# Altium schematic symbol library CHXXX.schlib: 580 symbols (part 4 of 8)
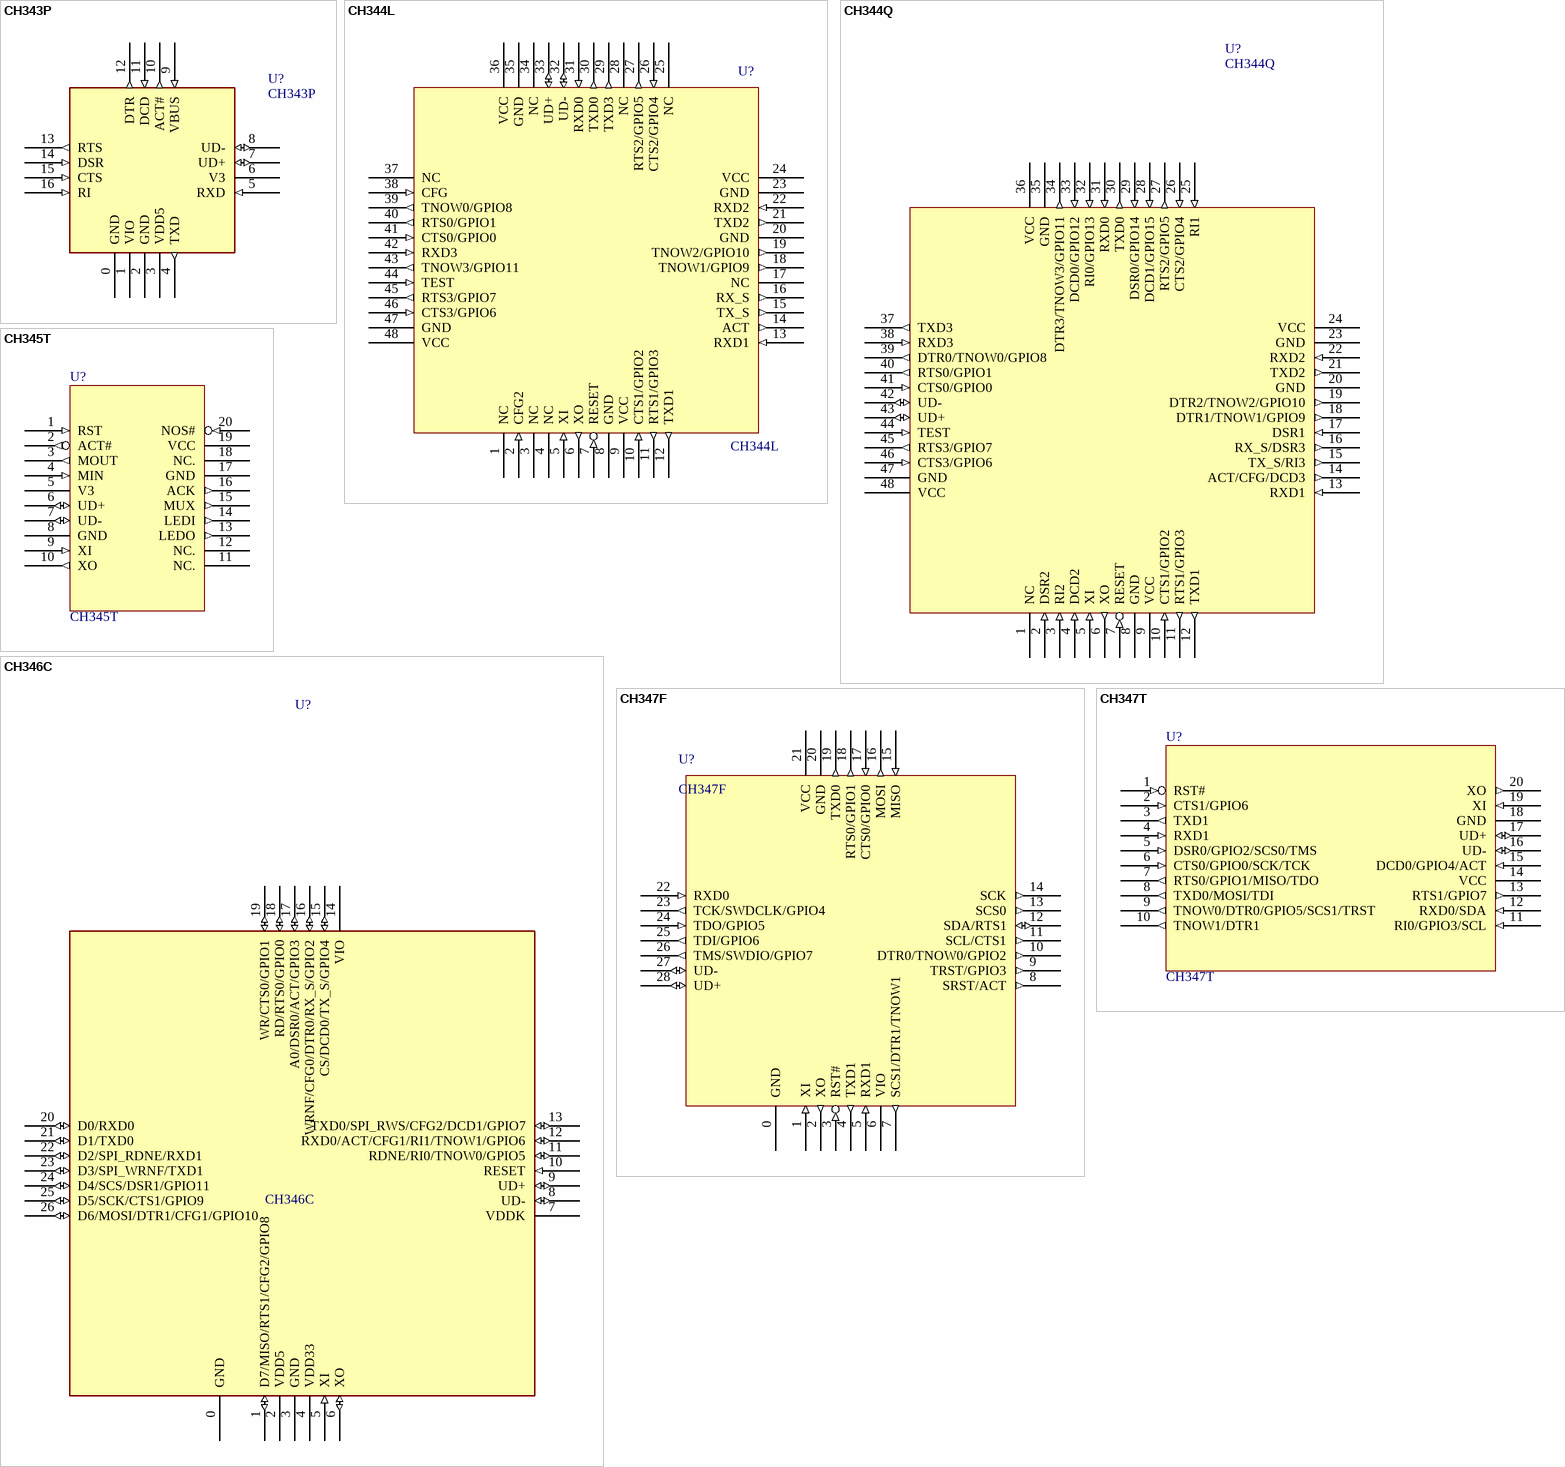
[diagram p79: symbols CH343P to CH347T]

## CH347F
designator U?
High Speed USB to UART + SPI + IIC + JTAG
footprint QFN28_4X4
pins: 0 GND (power), 1 XI (in), 2 XO (out), 3 RST# (in), 4 TXD1 (out), 5 RXD1 (in), 6 VIO (power), 7 SCS1/DTR1/TNOW1 (out), 8 SRST/ACT (out), 9 TRST/GPIO3 (out), 10 DTR0/TNOW0/GPIO2 (out), 11 SCL/CTS1 (out), 12 SDA/RTS1 (io), 13 SCS0 (out), 14 SCK (out), 15 MISO (in), 16 MOSI (out), 17 CTS0/GPIO0 (in), 18 RTS0/GPIO1 (out), 19 TXD0 (out), 20 GND (power), 21 VCC (power), 22 RXD0 (in), 23 TCK/SWDCLK/GPIO4 (out), 24 TDO/GPIO5 (in), 25 TDI/GPIO6 (out), 26 TMS/SWDIO/GPIO7 (out), 27 UD- (io), 28 UD+ (io)

## CH347T
designator U?
High Speed USB to UART / SPI / IIC / JTAG
footprint TSSOP20
pins: 1 RST# (in), 2 CTS1/GPIO6 (in), 3 TXD1 (out), 4 RXD1 (in), 5 DSR0/GPIO2/SCS0/TMS (in), 6 CTS0/GPIO0/SCK/TCK (in), 7 RTS0/GPIO1/MISO/TDO (out), 8 TXD0/MOSI/TDI (out), 9 TNOW0/DTR0/GPIO5/SCS1/TRST (out), 10 TNOW1/DTR1 (out), 11 RI0/GPIO3/SCL (in), 12 RXD0/SDA (in), 13 RTS1/GPIO7 (out), 14 VCC (power), 15 DCD0/GPIO4/ACT (in), 16 UD- (io), 17 UD+ (io), 18 GND (power), 19 XI (in), 20 XO (out)

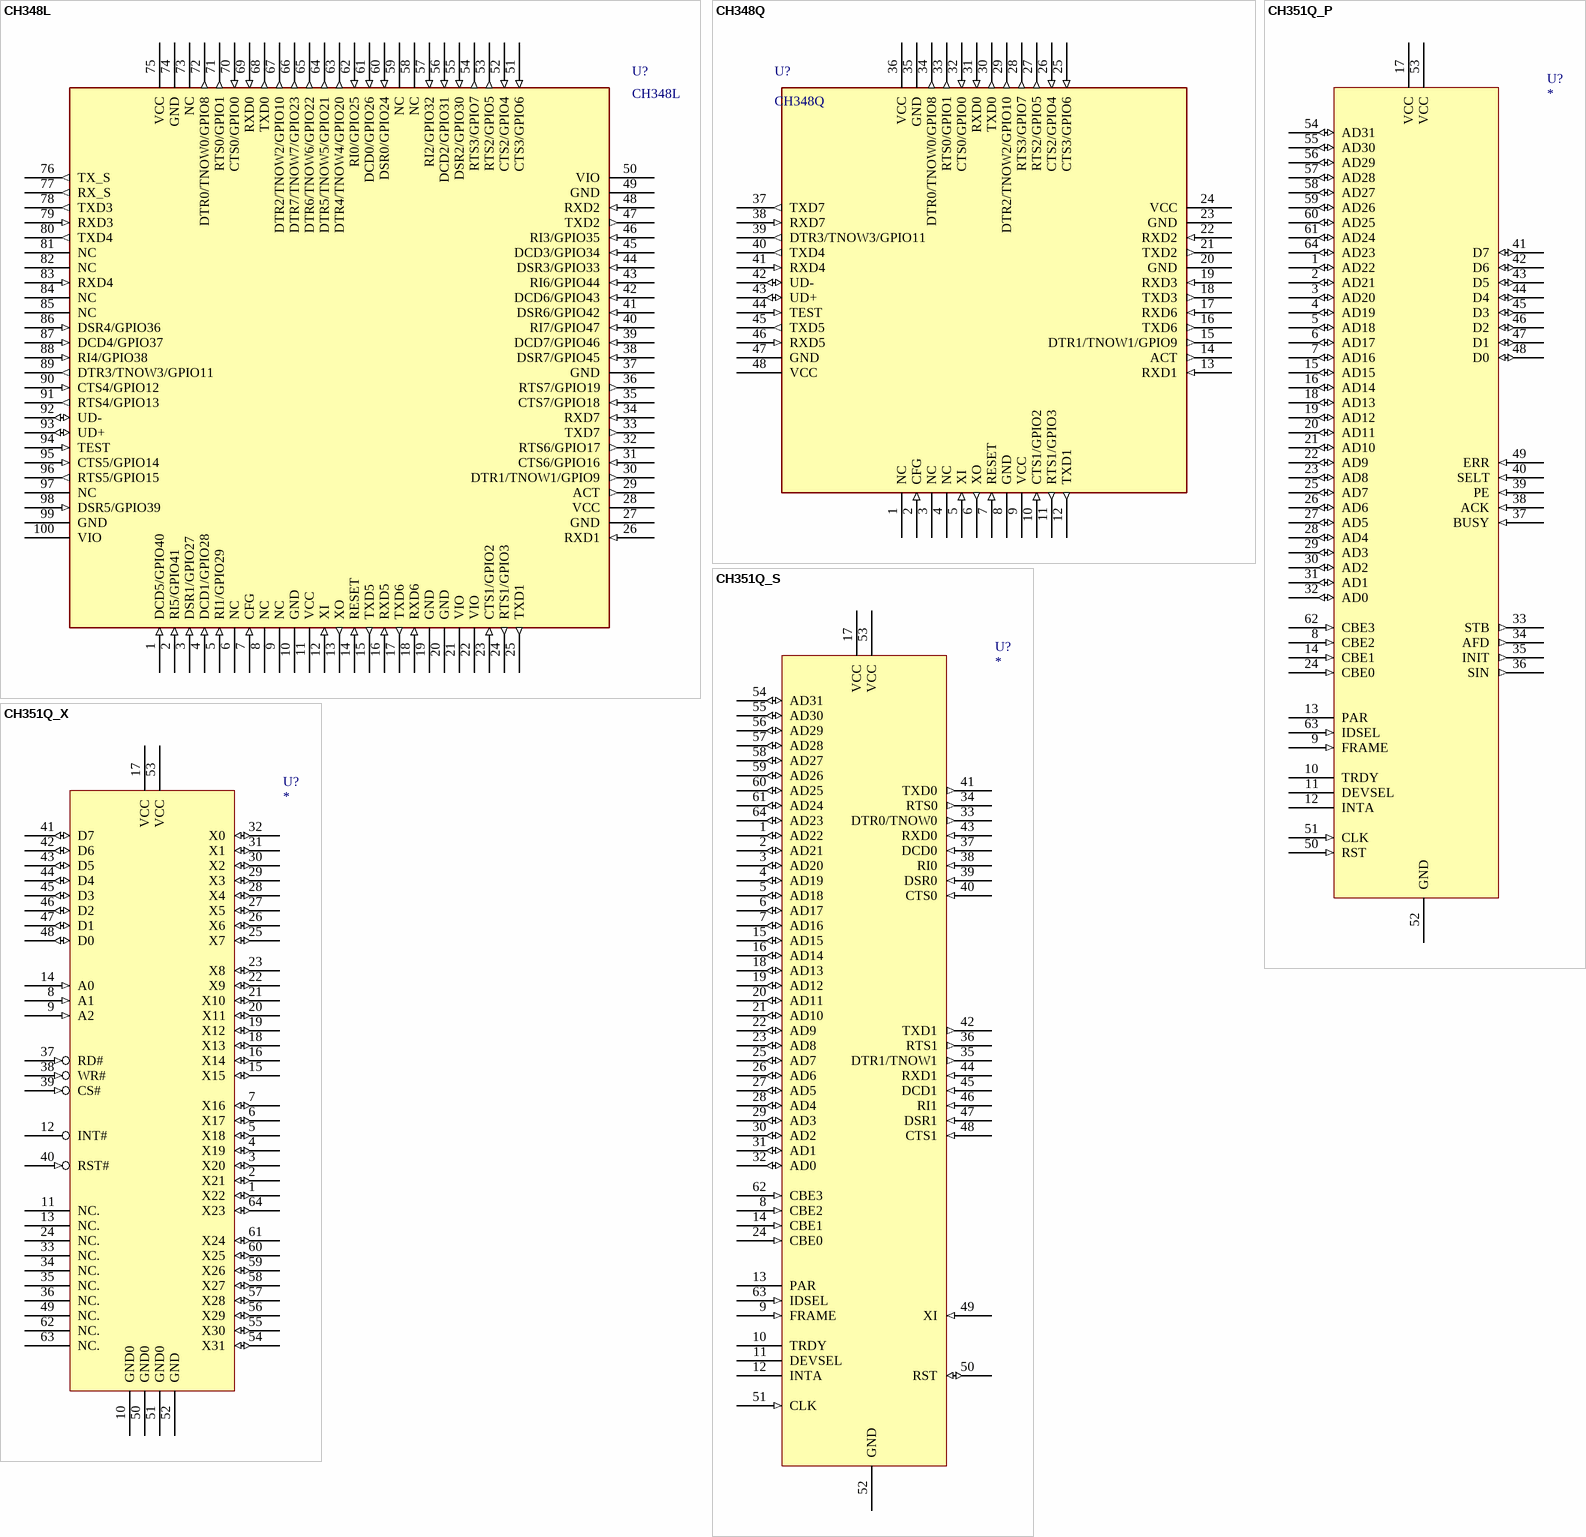
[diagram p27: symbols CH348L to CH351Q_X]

## CH348L
designator U?
High Speed USB to eight enhanced TTL Serial / 8 *UART
footprint LQFP100
pins: 1 DCD5/GPIO40 (in), 2 RI5/GPIO41 (in), 3 DSR1/GPIO27 (in), 4 DCD1/GPIO28 (in), 5 RI1/GPIO29 (in), 6 NC, 7 CFG (in), 8 NC, 9 NC, 10 GND (power), 11 VCC (power), 12 XI (in), 13 XO (out), 14 RESET (in), 15 TXD5 (out), 16 RXD5 (in), 17 TXD6 (out), 18 RXD6 (in), 19 GND (power), 20 GND (power), 21 VIO (power), 22 VIO (power), 23 CTS1/GPIO2 (in), 24 RTS1/GPIO3 (out), 25 TXD1 (out), 26 RXD1 (in), 27 GND (power), 28 VCC (power), 29 ACT (out), 30 DTR1/TNOW1/GPIO9 (out), 31 CTS6/GPIO16 (in), 32 RTS6/GPIO17 (out), 33 TXD7 (out), 34 RXD7 (in), 35 CTS7/GPIO18 (in), 36 RTS7/GPIO19 (out), 37 GND (power), 38 DSR7/GPIO45 (in), 39 DCD7/GPIO46 (in), 40 RI7/GPIO47 (in), 41 DSR6/GPIO42 (in), 42 DCD6/GPIO43 (in), 43 RI6/GPIO44 (in), 44 DSR3/GPIO33 (in), 45 DCD3/GPIO34 (in), 46 RI3/GPIO35 (in), 47 TXD2 (out), 48 RXD2 (in), 49 GND (power), 50 VIO (power), 51 CTS3/GPIO6 (in), 52 CTS2/GPIO4 (in), 53 RTS2/GPIO5 (out), 54 RTS3/GPIO7 (out), 55 DSR2/GPIO30 (in), 56 DCD2/GPIO31 (in), 57 RI2/GPIO32 (in), 58 NC, 59 NC, 60 DSR0/GPIO24 (in), 61 DCD0/GPIO26 (in), 62 RI0/GPIO25 (in), 63 DTR4/TNOW4/GPIO20 (out), 64 DTR5/TNOW5/GPIO21 (out), 65 DTR6/TNOW6/GPIO22 (out), 66 DTR7/TNOW7/GPIO23 (out), 67 DTR2/TNOW2/GPIO10 (out), 68 TXD0 (out), 69 RXD0 (in), 70 CTS0/GPIO0 (in), 71 RTS0/GPIO1 (out), 72 DTR0/TNOW0/GPIO8 (out), 73 NC, 74 GND (power), 75 VCC (power), 76 TX_S (out), 77 RX_S (out), 78 TXD3 (out), 79 RXD3 (in), 80 TXD4 (out), 81 NC, 82 NC, 83 RXD4 (in), 84 NC, 85 NC, 86 DSR4/GPIO36 (in), 87 DCD4/GPIO37 (in), 88 RI4/GPIO38 (in), 89 DTR3/TNOW3/GPIO11 (out), 90 CTS4/GPIO12 (in), 91 RTS4/GPIO13 (out), 92 UD- (io), 93 UD+ (io), 94 TEST (in), 95 CTS5/GPIO14 (in), 96 RTS5/GPIO15 (out), 97 NC, 98 DSR5/GPIO39 (in), 99 GND (power), 100 VIO (power)

## CH348Q
designator U?
High Speed USB to eight enhanced TTL Serial / 8 *UART
footprint LQFP48
pins: 1 NC, 2 CFG (in), 3 NC, 4 NC, 5 XI (in), 6 XO (out), 7 RESET (in), 8 GND (power), 9 VCC (power), 10 CTS1/GPIO2 (in), 11 RTS1/GPIO3 (out), 12 TXD1 (out), 13 RXD1 (in), 14 ACT (out), 15 DTR1/TNOW1/GPIO9 (out), 16 TXD6 (out), 17 RXD6 (in), 18 TXD3 (out), 19 RXD3 (in), 20 GND (power), 21 TXD2 (out), 22 RXD2 (in), 23 GND (power), 24 VCC (power), 25 CTS3/GPIO6 (in), 26 CTS2/GPIO4 (in), 27 RTS2/GPIO5 (out), 28 RTS3/GPIO7 (out), 29 DTR2/TNOW2/GPIO10 (out), 30 TXD0 (out), 31 RXD0 (in), 32 CTS0/GPIO0 (in), 33 RTS0/GPIO1 (out), 34 DTR0/TNOW0/GPIO8 (out), 35 GND (power), 36 VCC (power), 37 TXD7 (out), 38 RXD7 (in), 39 DTR3/TNOW3/GPIO11 (out), 40 TXD4 (out), 41 RXD4 (in), 42 UD- (io), 43 UD+ (io), 44 TEST (in), 45 TXD5 (out), 46 RXD5 (in), 47 GND (power), 48 VCC (power)

## CH351Q_P
designator U?
PCI to 1P: Print Port / Parallel
footprint LQFP64
pins: 1 AD22 (io), 2 AD21 (io), 3 AD20 (io), 4 AD19 (io), 5 AD18 (io), 6 AD17 (io), 7 AD16 (io), 8 CBE2 (in), 9 FRAME (in), 10 TRDY (hiz), 11 DEVSEL (hiz), 12 INTA (hiz), 13 PAR (hiz), 14 CBE1 (in), 15 AD15 (io), 16 AD14 (io), 17 VCC (power), 18 AD13 (io), 19 AD12 (io), 20 AD11 (io), 21 AD10 (io), 22 AD9 (io), 23 AD8 (io), 24 CBE0 (in), 25 AD7 (io), 26 AD6 (io), 27 AD5 (io), 28 AD4 (io), 29 AD3 (io), 30 AD2 (io), 31 AD1 (io), 32 AD0 (io), 33 STB (out), 34 AFD (out), 35 INIT (out), 36 SIN (out), 37 BUSY (in), 38 ACK (in), 39 PE (in), 40 SELT (in), 41 D7 (io), 42 D6 (io), 43 D5 (io), 44 D4 (io), 45 D3 (io), 46 D2 (io), 47 D1 (io), 48 D0 (io), 49 ERR (in), 50 RST (in), 51 CLK (in), 52 GND (power), 53 VCC (power), 54 AD31 (io), 55 AD30 (io), 56 AD29 (io), 57 AD28 (io), 58 AD27 (io), 59 AD26 (io), 60 AD25 (io), 61 AD24 (io), 62 CBE3 (in), 63 IDSEL (in), 64 AD23 (io)

## CH351Q_S
designator U?
PCI to 2S: Dual 16C550 UART, TTL Serial*2
footprint LQFP64
pins: 1 AD22 (io), 2 AD21 (io), 3 AD20 (io), 4 AD19 (io), 5 AD18 (io), 6 AD17 (io), 7 AD16 (io), 8 CBE2 (in), 9 FRAME (in), 10 TRDY (hiz), 11 DEVSEL (hiz), 12 INTA (hiz), 13 PAR (hiz), 14 CBE1 (in), 15 AD15 (io), 16 AD14 (io), 17 VCC (power), 18 AD13 (io), 19 AD12 (io), 20 AD11 (io), 21 AD10 (io), 22 AD9 (io), 23 AD8 (io), 24 CBE0 (in), 25 AD7 (io), 26 AD6 (io), 27 AD5 (io), 28 AD4 (io), 29 AD3 (io), 30 AD2 (io), 31 AD1 (io), 32 AD0 (io), 33 DTR0/TNOW0 (out), 34 RTS0 (out), 35 DTR1/TNOW1 (out), 36 RTS1 (out), 37 DCD0 (in), 38 RI0 (in), 39 DSR0 (in), 40 CTS0 (in), 41 TXD0 (out), 42 TXD1 (out), 43 RXD0 (in), 44 RXD1 (in), 45 DCD1 (in), 46 RI1 (in), 47 DSR1 (in), 48 CTS1 (in), 49 XI (in), 50 RST (io), 51 CLK (in), 52 GND (power), 53 VCC (power), 54 AD31 (io), 55 AD30 (io), 56 AD29 (io), 57 AD28 (io), 58 AD27 (io), 59 AD26 (io), 60 AD25 (io), 61 AD24 (io), 62 CBE3 (in), 63 IDSEL (in), 64 AD23 (io)

## CH351Q_X
designator U?
Parallel I/O expander, 32 GPIO
footprint LQFP64
pins: 1 X22 (io), 2 X21 (io), 3 X20 (io), 4 X19 (io), 5 X18 (io), 6 X17 (io), 7 X16 (io), 8 A1 (in), 9 A2 (in), 10 GND0 (power), 11 NC., 12 INT# (oc), 13 NC., 14 A0 (in), 15 X15 (io), 16 X14 (io), 17 VCC (power), 18 X13 (io), 19 X12 (io), 20 X11 (io), 21 X10 (io), 22 X9 (io), 23 X8 (io), 24 NC., 25 X7 (io), 26 X6 (io), 27 X5 (io), 28 X4 (io), 29 X3 (io), 30 X2 (io), 31 X1 (io), 32 X0 (io), 33 NC., 34 NC., 35 NC., 36 NC., 37 RD# (in), 38 WR# (in), 39 CS# (in), 40 RST# (in), 41 D7 (io), 42 D6 (io), 43 D5 (io), 44 D4 (io), 45 D3 (io), 46 D2 (io), 47 D1 (io), 48 D0 (io), 49 NC., 50 GND0 (power), 51 GND0 (power), 52 GND (power), 53 VCC (power), 54 X31 (io), 55 X30 (io), 56 X29 (io), 57 X28 (io), 58 X27 (io), 59 X26 (io), 60 X25 (io), 61 X24 (io), 62 NC., 63 NC., 64 X23 (io)

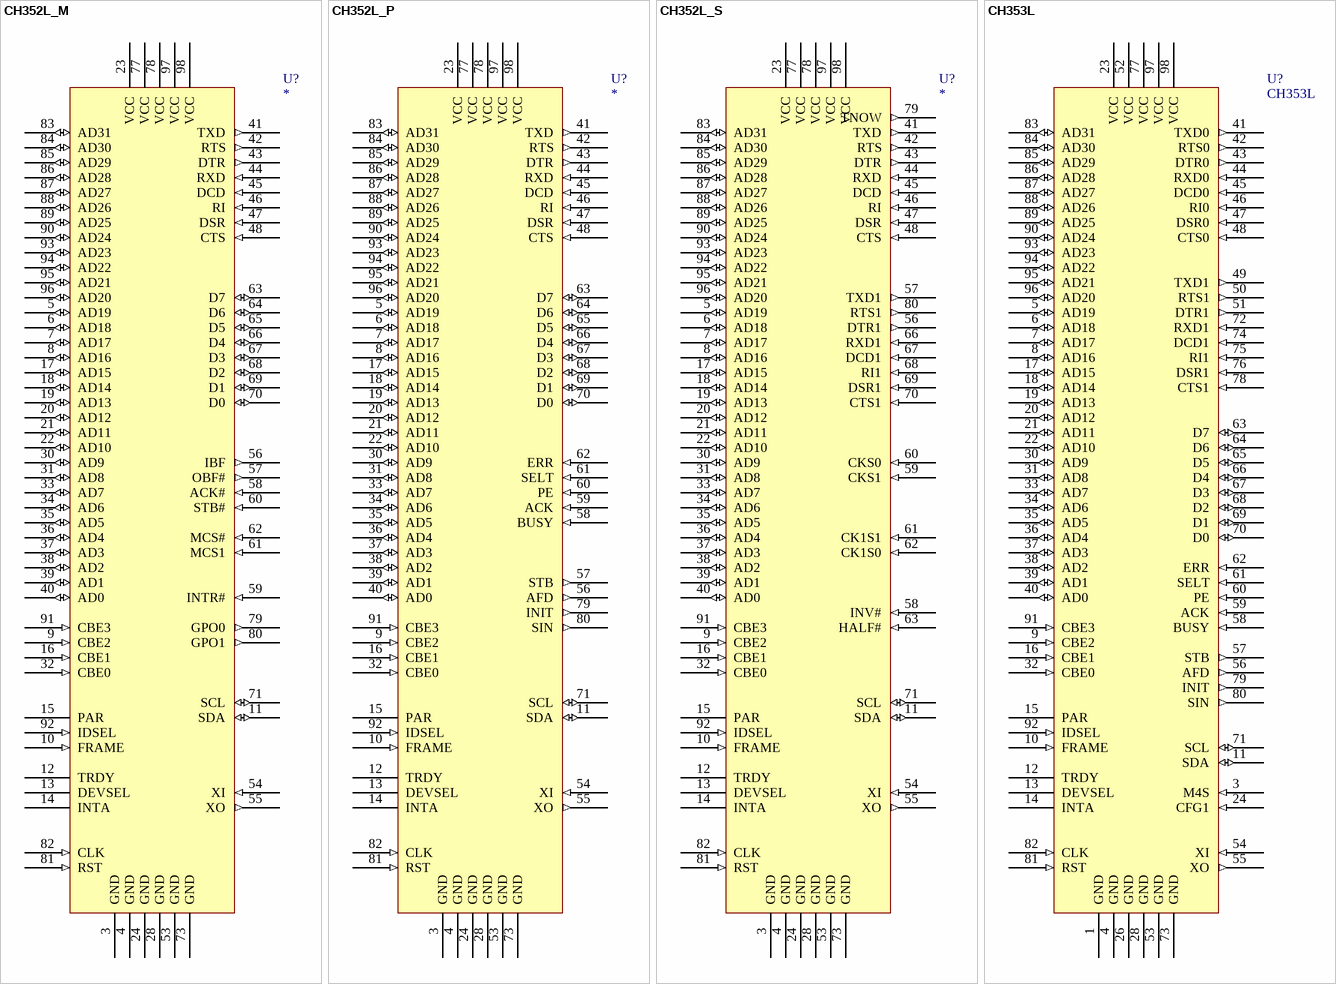
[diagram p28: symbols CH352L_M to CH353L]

## CH352L_M
designator U?
PCI to 8255 mode 2 Parallel for MCU and 16C550 UART / IrDA
footprint LQFP100
pins: 3 GND (power), 4 GND (power), 5 AD19 (io), 6 AD18 (io), 7 AD17 (io), 8 AD16 (io), 9 CBE2 (in), 10 FRAME (in), 11 SDA (io), 12 TRDY (hiz), 13 DEVSEL (hiz), 14 INTA (hiz), 15 PAR (hiz), 16 CBE1 (in), 17 AD15 (io), 18 AD14 (io), 19 AD13 (io), 20 AD12 (io), 21 AD11 (io), 22 AD10 (io), 23 VCC (power), 24 GND (power), 28 GND (power), 30 AD9 (io), 31 AD8 (io), 32 CBE0 (in), 33 AD7 (io), 34 AD6 (io), 35 AD5 (io), 36 AD4 (io), 37 AD3 (io), 38 AD2 (io), 39 AD1 (io), 40 AD0 (io), 41 TXD (out), 42 RTS (out), 43 DTR (out), 44 RXD (in), 45 DCD (in), 46 RI (in), 47 DSR (in), 48 CTS (in), 53 GND (power), 54 XI (in), 55 XO (out), 56 IBF (out), 57 OBF# (out), 58 ACK# (in), 59 INTR# (in), 60 STB# (in), 61 MCS1 (in), 62 MCS# (in), 63 D7 (io), 64 D6 (io), 65 D5 (io), 66 D4 (io), 67 D3 (io), 68 D2 (io), 69 D1 (io), 70 D0 (io), 71 SCL (io), 73 GND (power), 77 VCC (power), 78 VCC (power), 79 GPO0 (out), 80 GPO1 (out), 81 RST (in), 82 CLK (in), 83 AD31 (io), 84 AD30 (io), 85 AD29 (io), 86 AD28 (io), 87 AD27 (io), 88 AD26 (io), 89 AD25 (io), 90 AD24 (io), 91 CBE3 (in), 92 IDSEL (in), 93 AD23 (io), 94 AD22 (io), 95 AD21 (io), 96 AD20 (io), 97 VCC (power), 98 VCC (power)

## CH352L_P
designator U?
PCI to 1S1P: Print Port / Parallel and 16C550 UART / IrDA
footprint LQFP100
pins: 3 GND (power), 4 GND (power), 5 AD19 (io), 6 AD18 (io), 7 AD17 (io), 8 AD16 (io), 9 CBE2 (in), 10 FRAME (in), 11 SDA (io), 12 TRDY (hiz), 13 DEVSEL (hiz), 14 INTA (hiz), 15 PAR (hiz), 16 CBE1 (in), 17 AD15 (io), 18 AD14 (io), 19 AD13 (io), 20 AD12 (io), 21 AD11 (io), 22 AD10 (io), 23 VCC (power), 24 GND (power), 28 GND (power), 30 AD9 (io), 31 AD8 (io), 32 CBE0 (in), 33 AD7 (io), 34 AD6 (io), 35 AD5 (io), 36 AD4 (io), 37 AD3 (io), 38 AD2 (io), 39 AD1 (io), 40 AD0 (io), 41 TXD (out), 42 RTS (out), 43 DTR (out), 44 RXD (in), 45 DCD (in), 46 RI (in), 47 DSR (in), 48 CTS (in), 53 GND (power), 54 XI (in), 55 XO (out), 56 AFD (out), 57 STB (out), 58 BUSY (in), 59 ACK (in), 60 PE (in), 61 SELT (in), 62 ERR (in), 63 D7 (io), 64 D6 (io), 65 D5 (io), 66 D4 (io), 67 D3 (io), 68 D2 (io), 69 D1 (io), 70 D0 (io), 71 SCL (io), 73 GND (power), 77 VCC (power), 78 VCC (power), 79 INIT (out), 80 SIN (out), 81 RST (in), 82 CLK (in), 83 AD31 (io), 84 AD30 (io), 85 AD29 (io), 86 AD28 (io), 87 AD27 (io), 88 AD26 (io), 89 AD25 (io), 90 AD24 (io), 91 CBE3 (in), 92 IDSEL (in), 93 AD23 (io), 94 AD22 (io), 95 AD21 (io), 96 AD20 (io), 97 VCC (power), 98 VCC (power)

## CH352L_S
designator U?
PCI to 2S: Dual 16C550 UART, TTL Serial*2 / IrDA*1
footprint LQFP100
pins: 3 GND (power), 4 GND (power), 5 AD19 (io), 6 AD18 (io), 7 AD17 (io), 8 AD16 (io), 9 CBE2 (in), 10 FRAME (in), 11 SDA (io), 12 TRDY (hiz), 13 DEVSEL (hiz), 14 INTA (hiz), 15 PAR (hiz), 16 CBE1 (in), 17 AD15 (io), 18 AD14 (io), 19 AD13 (io), 20 AD12 (io), 21 AD11 (io), 22 AD10 (io), 23 VCC (power), 24 GND (power), 28 GND (power), 30 AD9 (io), 31 AD8 (io), 32 CBE0 (in), 33 AD7 (io), 34 AD6 (io), 35 AD5 (io), 36 AD4 (io), 37 AD3 (io), 38 AD2 (io), 39 AD1 (io), 40 AD0 (io), 41 TXD (out), 42 RTS (out), 43 DTR (out), 44 RXD (in), 45 DCD (in), 46 RI (in), 47 DSR (in), 48 CTS (in), 53 GND (power), 54 XI (in), 55 XO (out), 56 DTR1 (out), 57 TXD1 (out), 58 INV# (in), 59 CKS1 (in), 60 CKS0 (in), 61 CK1S1 (in), 62 CK1S0 (in), 63 HALF# (in), 66 RXD1 (in), 67 DCD1 (in), 68 RI1 (in), 69 DSR1 (in), 70 CTS1 (in), 71 SCL (io), 73 GND (power), 77 VCC (power), 78 VCC (power), 79 TNOW (out), 80 RTS1 (out), 81 RST (in), 82 CLK (in), 83 AD31 (io), 84 AD30 (io), 85 AD29 (io), 86 AD28 (io), 87 AD27 (io), 88 AD26 (io), 89 AD25 (io), 90 AD24 (io), 91 CBE3 (in), 92 IDSEL (in), 93 AD23 (io), 94 AD22 (io), 95 AD21 (io), 96 AD20 (io), 97 VCC (power), 98 VCC (power)

## CH353L
designator U?
PCI to 2S1P: Print Port / Parallel and Dual 16C550 UART / IrDA*1
footprint LQFP100
pins: 1 GND (power), 3 M4S (in), 4 GND (power), 5 AD19 (io), 6 AD18 (io), 7 AD17 (io), 8 AD16 (io), 9 CBE2 (in), 10 FRAME (in), 11 SDA (io), 12 TRDY (hiz), 13 DEVSEL (hiz), 14 INTA (hiz), 15 PAR (hiz), 16 CBE1 (in), 17 AD15 (io), 18 AD14 (io), 19 AD13 (io), 20 AD12 (io), 21 AD11 (io), 22 AD10 (io), 23 VCC (power), 24 CFG1 (in), 26 GND (power), 28 GND (power), 30 AD9 (io), 31 AD8 (io), 32 CBE0 (in), 33 AD7 (io), 34 AD6 (io), 35 AD5 (io), 36 AD4 (io), 37 AD3 (io), 38 AD2 (io), 39 AD1 (io), 40 AD0 (io), 41 TXD0 (out), 42 RTS0 (out), 43 DTR0 (out), 44 RXD0 (in), 45 DCD0 (in), 46 RI0 (in), 47 DSR0 (in), 48 CTS0 (in), 49 TXD1 (out), 50 RTS1 (out), 51 DTR1 (out), 52 VCC (power), 53 GND (power), 54 XI (in), 55 XO (out), 56 AFD (out), 57 STB (out), 58 BUSY (in), 59 ACK (in), 60 PE (in), 61 SELT (in), 62 ERR (in), 63 D7 (io), 64 D6 (io), 65 D5 (io), 66 D4 (io), 67 D3 (io), 68 D2 (io), 69 D1 (io), 70 D0 (io), 71 SCL (io), 72 RXD1 (in), 73 GND (power), 74 DCD1 (in), 75 RI1 (in), 76 DSR1 (in), 77 VCC (power), 78 CTS1 (in), 79 INIT (out), 80 SIN (out), 81 RST (in), 82 CLK (in), 83 AD31 (io), 84 AD30 (io), 85 AD29 (io), 86 AD28 (io), 87 AD27 (io), 88 AD26 (io), 89 AD25 (io), 90 AD24 (io), 91 CBE3 (in), 92 IDSEL (in), 93 AD23 (io), 94 AD22 (io), 95 AD21 (io), 96 AD20 (io), 97 VCC (power), 98 VCC (power)

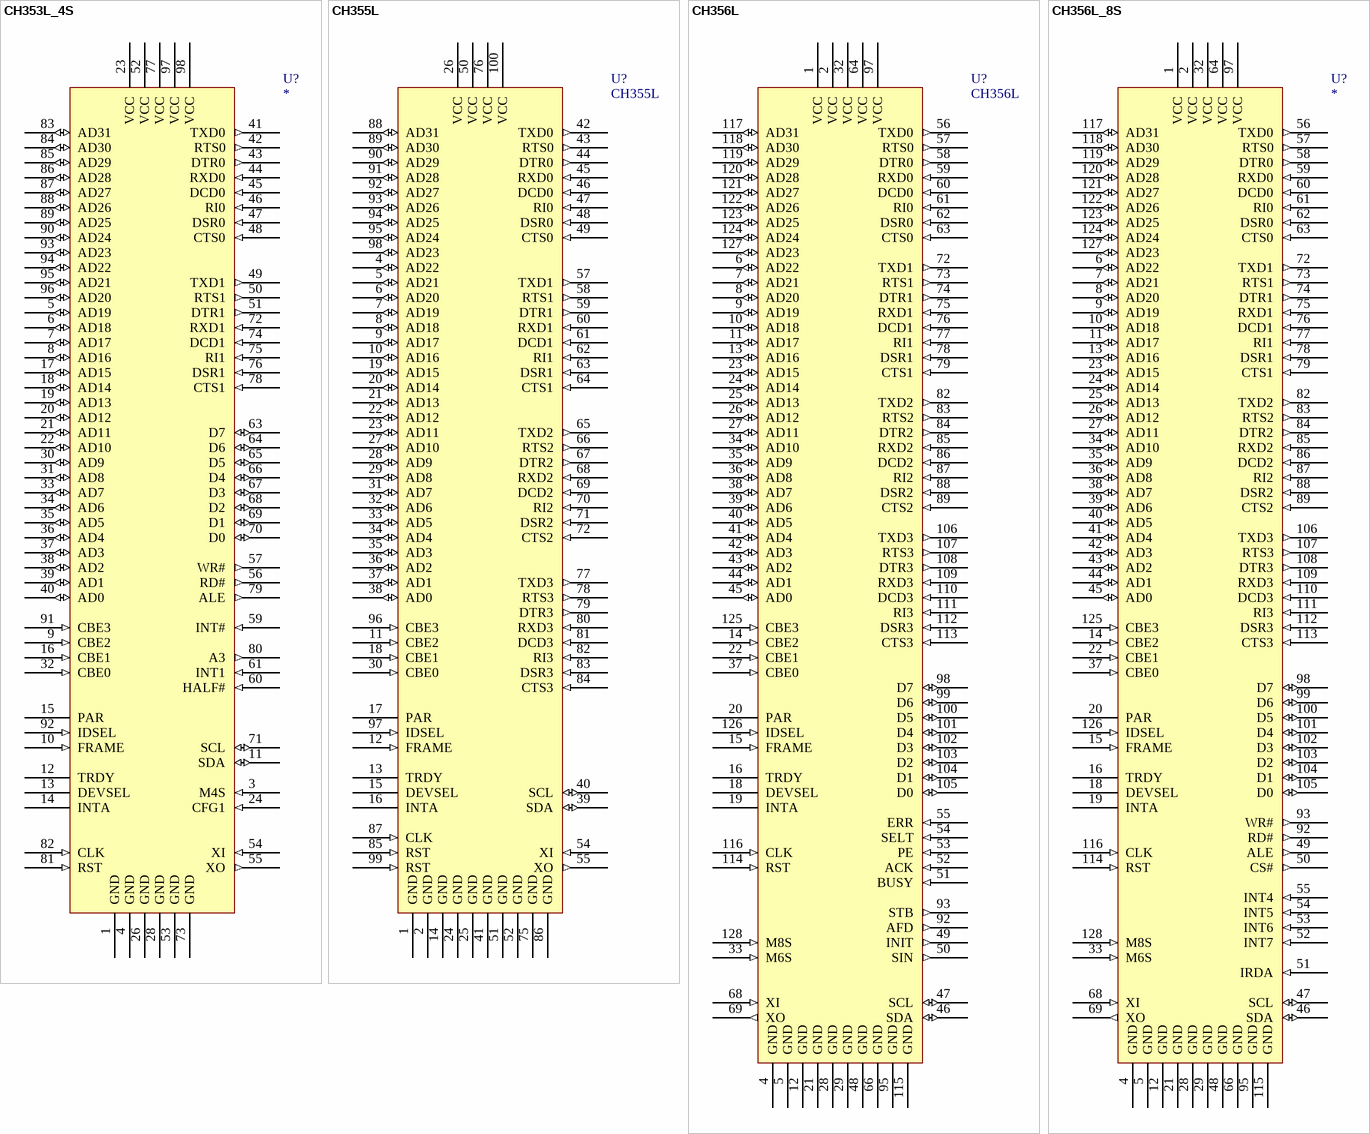
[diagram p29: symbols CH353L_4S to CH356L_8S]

## CH353L_4S
designator U?
PCI to 4S: Dual 16C550 UART + external dual, TTL Serial*4
footprint LQFP100
pins: 1 GND (power), 3 M4S (in), 4 GND (power), 5 AD19 (io), 6 AD18 (io), 7 AD17 (io), 8 AD16 (io), 9 CBE2 (in), 10 FRAME (in), 11 SDA (io), 12 TRDY (hiz), 13 DEVSEL (hiz), 14 INTA (hiz), 15 PAR (hiz), 16 CBE1 (in), 17 AD15 (io), 18 AD14 (io), 19 AD13 (io), 20 AD12 (io), 21 AD11 (io), 22 AD10 (io), 23 VCC (power), 24 CFG1 (in), 26 GND (power), 28 GND (power), 30 AD9 (io), 31 AD8 (io), 32 CBE0 (in), 33 AD7 (io), 34 AD6 (io), 35 AD5 (io), 36 AD4 (io), 37 AD3 (io), 38 AD2 (io), 39 AD1 (io), 40 AD0 (io), 41 TXD0 (out), 42 RTS0 (out), 43 DTR0 (out), 44 RXD0 (in), 45 DCD0 (in), 46 RI0 (in), 47 DSR0 (in), 48 CTS0 (in), 49 TXD1 (out), 50 RTS1 (out), 51 DTR1 (out), 52 VCC (power), 53 GND (power), 54 XI (in), 55 XO (out), 56 RD# (out), 57 WR# (out), 59 INT# (in), 60 HALF# (in), 61 INT1 (in), 63 D7 (io), 64 D6 (io), 65 D5 (io), 66 D4 (io), 67 D3 (io), 68 D2 (io), 69 D1 (io), 70 D0 (io), 71 SCL (io), 72 RXD1 (in), 73 GND (power), 74 DCD1 (in), 75 RI1 (in), 76 DSR1 (in), 77 VCC (power), 78 CTS1 (in), 79 ALE (out), 80 A3 (out), 81 RST (in), 82 CLK (in), 83 AD31 (io), 84 AD30 (io), 85 AD29 (io), 86 AD28 (io), 87 AD27 (io), 88 AD26 (io), 89 AD25 (io), 90 AD24 (io), 91 CBE3 (in), 92 IDSEL (in), 93 AD23 (io), 94 AD22 (io), 95 AD21 (io), 96 AD20 (io), 97 VCC (power), 98 VCC (power)

## CH355L
designator U?
PCI to 4S: Quad 16C550 UART, TTL Serial*4 / IrDA*1
footprint LQFP100
pins: 1 GND (power), 2 GND (power), 4 AD22 (io), 5 AD21 (io), 6 AD20 (io), 7 AD19 (io), 8 AD18 (io), 9 AD17 (io), 10 AD16 (io), 11 CBE2 (in), 12 FRAME (in), 13 TRDY (hiz), 14 GND (power), 15 DEVSEL (hiz), 16 INTA (hiz), 17 PAR (hiz), 18 CBE1 (in), 19 AD15 (io), 20 AD14 (io), 21 AD13 (io), 22 AD12 (io), 23 AD11 (io), 24 GND (power), 25 GND (power), 26 VCC (power), 27 AD10 (io), 28 AD9 (io), 29 AD8 (io), 30 CBE0 (in), 31 AD7 (io), 32 AD6 (io), 33 AD5 (io), 34 AD4 (io), 35 AD3 (io), 36 AD2 (io), 37 AD1 (io), 38 AD0 (io), 39 SDA (io), 40 SCL (io), 41 GND (power), 42 TXD0 (out), 43 RTS0 (out), 44 DTR0 (out), 45 RXD0 (in), 46 DCD0 (in), 47 RI0 (in), 48 DSR0 (in), 49 CTS0 (in), 50 VCC (power), 51 GND (power), 52 GND (power), 54 XI (in), 55 XO (out), 57 TXD1 (out), 58 RTS1 (out), 59 DTR1 (out), 60 RXD1 (in), 61 DCD1 (in), 62 RI1 (in), 63 DSR1 (in), 64 CTS1 (in), 65 TXD2 (out), 66 RTS2 (out), 67 DTR2 (out), 68 RXD2 (in), 69 DCD2 (in), 70 RI2 (in), 71 DSR2 (in), 72 CTS2 (in), 75 GND (power), 76 VCC (power), 77 TXD3 (out), 78 RTS3 (out), 79 DTR3 (out), 80 RXD3 (in), 81 DCD3 (in), 82 RI3 (in), 83 DSR3 (in), 84 CTS3 (in), 85 RST (in), 86 GND (power), 87 CLK (in), 88 AD31 (io), 89 AD30 (io), 90 AD29 (io), 91 AD28 (io), 92 AD27 (io), 93 AD26 (io), 94 AD25 (io), 95 AD24 (io), 96 CBE3 (in), 97 IDSEL (in), 98 AD23 (io), 99 RST (in), 100 VCC (power)

## CH356L
designator U?
PCI to 4S1P: Print Port / Parallel and Quad 16C550 UART / IrDA*1
footprint LQFP128
pins: 1 VCC (power), 2 VCC (power), 4 GND (power), 5 GND (power), 6 AD22 (io), 7 AD21 (io), 8 AD20 (io), 9 AD19 (io), 10 AD18 (io), 11 AD17 (io), 12 GND (power), 13 AD16 (io), 14 CBE2 (in), 15 FRAME (in), 16 TRDY (hiz), 18 DEVSEL (hiz), 19 INTA (hiz), 20 PAR (hiz), 21 GND (power), 22 CBE1 (in), 23 AD15 (io), 24 AD14 (io), 25 AD13 (io), 26 AD12 (io), 27 AD11 (io), 28 GND (power), 29 GND (power), 32 VCC (power), 33 M6S (in), 34 AD10 (io), 35 AD9 (io), 36 AD8 (io), 37 CBE0 (in), 38 AD7 (io), 39 AD6 (io), 40 AD5 (io), 41 AD4 (io), 42 AD3 (io), 43 AD2 (io), 44 AD1 (io), 45 AD0 (io), 46 SDA (io), 47 SCL (io), 48 GND (power), 49 INIT (out), 50 SIN (out), 51 BUSY (in), 52 ACK (in), 53 PE (in), 54 SELT (in), 55 ERR (in), 56 TXD0 (out), 57 RTS0 (out), 58 DTR0 (out), 59 RXD0 (in), 60 DCD0 (in), 61 RI0 (in), 62 DSR0 (in), 63 CTS0 (in), 64 VCC (power), 66 GND (power), 68 XI (in), 69 XO (out), 72 TXD1 (out), 73 RTS1 (out), 74 DTR1 (out), 75 RXD1 (in), 76 DCD1 (in), 77 RI1 (in), 78 DSR1 (in), 79 CTS1 (in), 82 TXD2 (out), 83 RTS2 (out), 84 DTR2 (out), 85 RXD2 (in), 86 DCD2 (in), 87 RI2 (in), 88 DSR2 (in), 89 CTS2 (in), 92 AFD (out), 93 STB (out), 95 GND (power), 97 VCC (power), 98 D7 (io), 99 D6 (io), 100 D5 (io), 101 D4 (io), 102 D3 (io), 103 D2 (io), 104 D1 (io), 105 D0 (io), 106 TXD3 (out), 107 RTS3 (out), 108 DTR3 (out), 109 RXD3 (in), 110 DCD3 (in), 111 RI3 (in), 112 DSR3 (in), 113 CTS3 (in), 114 RST (in), 115 GND (power), 116 CLK (in), 117 AD31 (io), 118 AD30 (io), 119 AD29 (io), 120 AD28 (io), 121 AD27 (io), 122 AD26 (io), 123 AD25 (io), 124 AD24 (io), 125 CBE3 (in), 126 IDSEL (in), 127 AD23 (io), 128 M8S (in)

## CH356L_8S
designator U?
PCI to 8S: Quad 16C550 UART + external Quad, TTL Serial*8
footprint LQFP128
pins: 1 VCC (power), 2 VCC (power), 4 GND (power), 5 GND (power), 6 AD22 (io), 7 AD21 (io), 8 AD20 (io), 9 AD19 (io), 10 AD18 (io), 11 AD17 (io), 12 GND (power), 13 AD16 (io), 14 CBE2 (in), 15 FRAME (in), 16 TRDY (hiz), 18 DEVSEL (hiz), 19 INTA (hiz), 20 PAR (hiz), 21 GND (power), 22 CBE1 (in), 23 AD15 (io), 24 AD14 (io), 25 AD13 (io), 26 AD12 (io), 27 AD11 (io), 28 GND (power), 29 GND (power), 32 VCC (power), 33 M6S (in), 34 AD10 (io), 35 AD9 (io), 36 AD8 (io), 37 CBE0 (in), 38 AD7 (io), 39 AD6 (io), 40 AD5 (io), 41 AD4 (io), 42 AD3 (io), 43 AD2 (io), 44 AD1 (io), 45 AD0 (io), 46 SDA (io), 47 SCL (io), 48 GND (power), 49 ALE (out), 50 CS# (out), 51 IRDA (in), 52 INT7 (in), 53 INT6 (in), 54 INT5 (in), 55 INT4 (in), 56 TXD0 (out), 57 RTS0 (out), 58 DTR0 (out), 59 RXD0 (in), 60 DCD0 (in), 61 RI0 (in), 62 DSR0 (in), 63 CTS0 (in), 64 VCC (power), 66 GND (power), 68 XI (in), 69 XO (out), 72 TXD1 (out), 73 RTS1 (out), 74 DTR1 (out), 75 RXD1 (in), 76 DCD1 (in), 77 RI1 (in), 78 DSR1 (in), 79 CTS1 (in), 82 TXD2 (out), 83 RTS2 (out), 84 DTR2 (out), 85 RXD2 (in), 86 DCD2 (in), 87 RI2 (in), 88 DSR2 (in), 89 CTS2 (in), 92 RD# (out), 93 WR# (out), 95 GND (power), 97 VCC (power), 98 D7 (io), 99 D6 (io), 100 D5 (io), 101 D4 (io), 102 D3 (io), 103 D2 (io), 104 D1 (io), 105 D0 (io), 106 TXD3 (out), 107 RTS3 (out), 108 DTR3 (out), 109 RXD3 (in), 110 DCD3 (in), 111 RI3 (in), 112 DSR3 (in), 113 CTS3 (in), 114 RST (in), 115 GND (power), 116 CLK (in), 117 AD31 (io), 118 AD30 (io), 119 AD29 (io), 120 AD28 (io), 121 AD27 (io), 122 AD26 (io), 123 AD25 (io), 124 AD24 (io), 125 CBE3 (in), 126 IDSEL (in), 127 AD23 (io), 128 M8S (in)

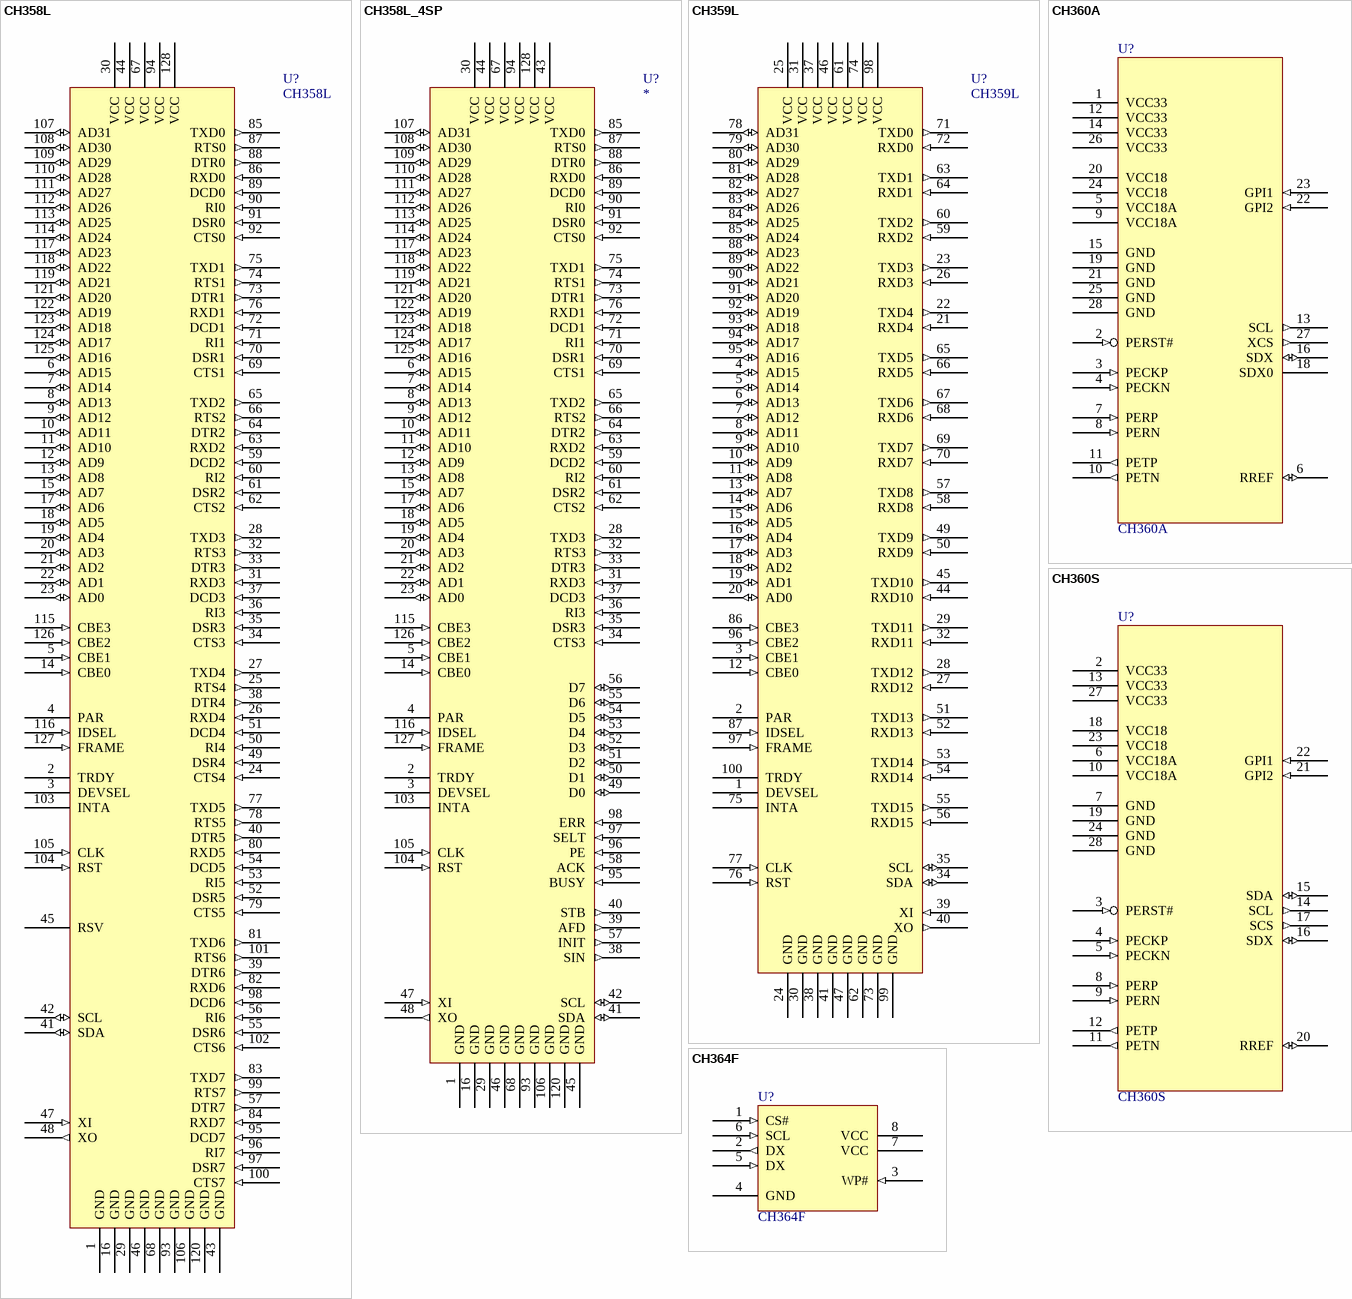
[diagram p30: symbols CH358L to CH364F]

## CH358L
designator U?
PCI to 8S: Oct 16C550 UART with 128 byte FIFO, TTL Serial*8 / IrDA*1
footprint LQFP128
pins: 1 GND (power), 2 TRDY (hiz), 3 DEVSEL (hiz), 4 PAR (hiz), 5 CBE1 (in), 6 AD15 (io), 7 AD14 (io), 8 AD13 (io), 9 AD12 (io), 10 AD11 (io), 11 AD10 (io), 12 AD9 (io), 13 AD8 (io), 14 CBE0 (in), 15 AD7 (io), 16 GND (power), 17 AD6 (io), 18 AD5 (io), 19 AD4 (io), 20 AD3 (io), 21 AD2 (io), 22 AD1 (io), 23 AD0 (io), 24 CTS4 (in), 25 RTS4 (out), 26 RXD4 (in), 27 TXD4 (out), 28 TXD3 (out), 29 GND (power), 30 VCC (power), 31 RXD3 (in), 32 RTS3 (out), 33 DTR3 (out), 34 CTS3 (in), 35 DSR3 (in), 36 RI3 (in), 37 DCD3 (in), 38 DTR4 (out), 39 DTR6 (out), 40 DTR5 (out), 41 SDA (io), 42 SCL (io), 43 GND (power), 44 VCC (power), 45 RSV, 46 GND (power), 47 XI (in), 48 XO (out), 49 DSR4 (in), 50 RI4 (in), 51 DCD4 (in), 52 DSR5 (in), 53 RI5 (in), 54 DCD5 (in), 55 DSR6 (in), 56 RI6 (in), 57 DTR7 (out), 59 DCD2 (in), 60 RI2 (in), 61 DSR2 (in), 62 CTS2 (in), 63 RXD2 (in), 64 DTR2 (out), 65 TXD2 (out), 66 RTS2 (out), 67 VCC (power), 68 GND (power), 69 CTS1 (in), 70 DSR1 (in), 71 RI1 (in), 72 DCD1 (in), 73 DTR1 (out), 74 RTS1 (out), 75 TXD1 (out), 76 RXD1 (in), 77 TXD5 (out), 78 RTS5 (out), 79 CTS5 (in), 80 RXD5 (in), 81 TXD6 (out), 82 RXD6 (in), 83 TXD7 (out), 84 RXD7 (in), 85 TXD0 (out), 86 RXD0 (in), 87 RTS0 (out), 88 DTR0 (out), 89 DCD0 (in), 90 RI0 (in), 91 DSR0 (in), 92 CTS0 (in), 93 GND (power), 94 VCC (power), 95 DCD7 (in), 96 RI7 (in), 97 DSR7 (in), 98 DCD6 (in), 99 RTS7 (out), 100 CTS7 (in), 101 RTS6 (out), 102 CTS6 (in), 103 INTA (hiz), 104 RST (in), 105 CLK (in), 106 GND (power), 107 AD31 (io), 108 AD30 (io), 109 AD29 (io), 110 AD28 (io), 111 AD27 (io), 112 AD26 (io), 113 AD25 (io), 114 AD24 (io), 115 CBE3 (in), 116 IDSEL (in), 117 AD23 (io), 118 AD22 (io), 119 AD21 (io), 120 GND (power), 121 AD20 (io), 122 AD19 (io), 123 AD18 (io), 124 AD17 (io), 125 AD16 (io), 126 CBE2 (in), 127 FRAME (in), 128 VCC (power)

## CH358L_4SP
designator U?
PCI to 4S1P: Print Port / Parallel and Quad 16C550 UART with 128 byte FIFO
footprint LQFP128
pins: 1 GND (power), 2 TRDY (hiz), 3 DEVSEL (hiz), 4 PAR (hiz), 5 CBE1 (in), 6 AD15 (io), 7 AD14 (io), 8 AD13 (io), 9 AD12 (io), 10 AD11 (io), 11 AD10 (io), 12 AD9 (io), 13 AD8 (io), 14 CBE0 (in), 15 AD7 (io), 16 GND (power), 17 AD6 (io), 18 AD5 (io), 19 AD4 (io), 20 AD3 (io), 21 AD2 (io), 22 AD1 (io), 23 AD0 (io), 28 TXD3 (out), 29 GND (power), 30 VCC (power), 31 RXD3 (in), 32 RTS3 (out), 33 DTR3 (out), 34 CTS3 (in), 35 DSR3 (in), 36 RI3 (in), 37 DCD3 (in), 38 SIN (out), 39 AFD (out), 40 STB (out), 41 SDA (io), 42 SCL (io), 43 VCC (power), 44 VCC (power), 45 GND (power), 46 GND (power), 47 XI (in), 48 XO (out), 49 D0 (io), 50 D1 (io), 51 D2 (io), 52 D3 (io), 53 D4 (io), 54 D5 (io), 55 D6 (io), 56 D7 (io), 57 INIT (out), 58 ACK (in), 59 DCD2 (in), 60 RI2 (in), 61 DSR2 (in), 62 CTS2 (in), 63 RXD2 (in), 64 DTR2 (out), 65 TXD2 (out), 66 RTS2 (out), 67 VCC (power), 68 GND (power), 69 CTS1 (in), 70 DSR1 (in), 71 RI1 (in), 72 DCD1 (in), 73 DTR1 (out), 74 RTS1 (out), 75 TXD1 (out), 76 RXD1 (in), 85 TXD0 (out), 86 RXD0 (in), 87 RTS0 (out), 88 DTR0 (out), 89 DCD0 (in), 90 RI0 (in), 91 DSR0 (in), 92 CTS0 (in), 93 GND (power), 94 VCC (power), 95 BUSY (in), 96 PE (in), 97 SELT (in), 98 ERR (in), 103 INTA (hiz), 104 RST (in), 105 CLK (in), 106 GND (power), 107 AD31 (io), 108 AD30 (io), 109 AD29 (io), 110 AD28 (io), 111 AD27 (io), 112 AD26 (io), 113 AD25 (io), 114 AD24 (io), 115 CBE3 (in), 116 IDSEL (in), 117 AD23 (io), 118 AD22 (io), 119 AD21 (io), 120 GND (power), 121 AD20 (io), 122 AD19 (io), 123 AD18 (io), 124 AD17 (io), 125 AD16 (io), 126 CBE2 (in), 127 FRAME (in), 128 VCC (power)

## CH359L
designator U?
PCI to 16S: TTL 3 wire Serial*16, 128 byte FIFO, no modem
footprint LQFP100
pins: 1 DEVSEL (hiz), 2 PAR (hiz), 3 CBE1 (in), 4 AD15 (io), 5 AD14 (io), 6 AD13 (io), 7 AD12 (io), 8 AD11 (io), 9 AD10 (io), 10 AD9 (io), 11 AD8 (io), 12 CBE0 (in), 13 AD7 (io), 14 AD6 (io), 15 AD5 (io), 16 AD4 (io), 17 AD3 (io), 18 AD2 (io), 19 AD1 (io), 20 AD0 (io), 21 RXD4 (in), 22 TXD4 (out), 23 TXD3 (out), 24 GND (power), 25 VCC (power), 26 RXD3 (in), 27 RXD12 (in), 28 TXD12 (out), 29 TXD11 (out), 30 GND (power), 31 VCC (power), 32 RXD11 (in), 34 SDA (io), 35 SCL (io), 37 VCC (power), 38 GND (power), 39 XI (in), 40 XO (out), 41 GND (power), 44 RXD10 (in), 45 TXD10 (out), 46 VCC (power), 47 GND (power), 49 TXD9 (out), 50 RXD9 (in), 51 TXD13 (out), 52 RXD13 (in), 53 TXD14 (out), 54 RXD14 (in), 55 TXD15 (out), 56 RXD15 (in), 57 TXD8 (out), 58 RXD8 (in), 59 RXD2 (in), 60 TXD2 (out), 61 VCC (power), 62 GND (power), 63 TXD1 (out), 64 RXD1 (in), 65 TXD5 (out), 66 RXD5 (in), 67 TXD6 (out), 68 RXD6 (in), 69 TXD7 (out), 70 RXD7 (in), 71 TXD0 (out), 72 RXD0 (in), 73 GND (power), 74 VCC (power), 75 INTA (hiz), 76 RST (in), 77 CLK (in), 78 AD31 (io), 79 AD30 (io), 80 AD29 (io), 81 AD28 (io), 82 AD27 (io), 83 AD26 (io), 84 AD25 (io), 85 AD24 (io), 86 CBE3 (in), 87 IDSEL (in), 88 AD23 (io), 89 AD22 (io), 90 AD21 (io), 91 AD20 (io), 92 AD19 (io), 93 AD18 (io), 94 AD17 (io), 95 AD16 (io), 96 CBE2 (in), 97 FRAME (in), 98 VCC (power), 99 GND (power), 100 TRDY (hiz)

## CH360A
designator U?
PCIe Device embed FlashROM for Expansion ROM
footprint SOP28
pins: 1 VCC33 (power), 2 PERST# (in), 3 PECKP (in), 4 PECKN (in), 5 VCC18A (power), 6 RREF (io), 7 PERP (in), 8 PERN (in), 9 VCC18A (power), 10 PETN (out), 11 PETP (out), 12 VCC33 (power), 13 SCL (out), 14 VCC33 (power), 15 GND (power), 16 SDX (io), 18 SDX0 (hiz), 19 GND (power), 20 VCC18 (power), 21 GND (power), 22 GPI2 (in), 23 GPI1 (in), 24 VCC18 (power), 25 GND (power), 26 VCC33 (power), 27 XCS (out), 28 GND (power)

## CH360S
designator U?
PCIe Device for Expansion ROM
footprint SOP28
pins: 2 VCC33 (power), 3 PERST# (in), 4 PECKP (in), 5 PECKN (in), 6 VCC18A (power), 7 GND (power), 8 PERP (in), 9 PERN (in), 10 VCC18A (power), 11 PETN (out), 12 PETP (out), 13 VCC33 (power), 14 SCL (out), 15 SDA (io), 16 SDX (io), 17 SCS (out), 18 VCC18 (power), 19 GND (power), 20 RREF (io), 21 GPI2 (in), 22 GPI1 (in), 23 VCC18 (power), 24 GND (power), 27 VCC33 (power), 28 GND (power)

## CH364F
designator U?
Flash ROM, Member of CH364/CH366 chipsets
footprint SOP8
pins: 1 CS# (in), 2 DX (out), 3 WP# (in), 4 GND (power), 5 DX (in), 6 SCL (in), 7 VCC (power), 8 VCC (power)

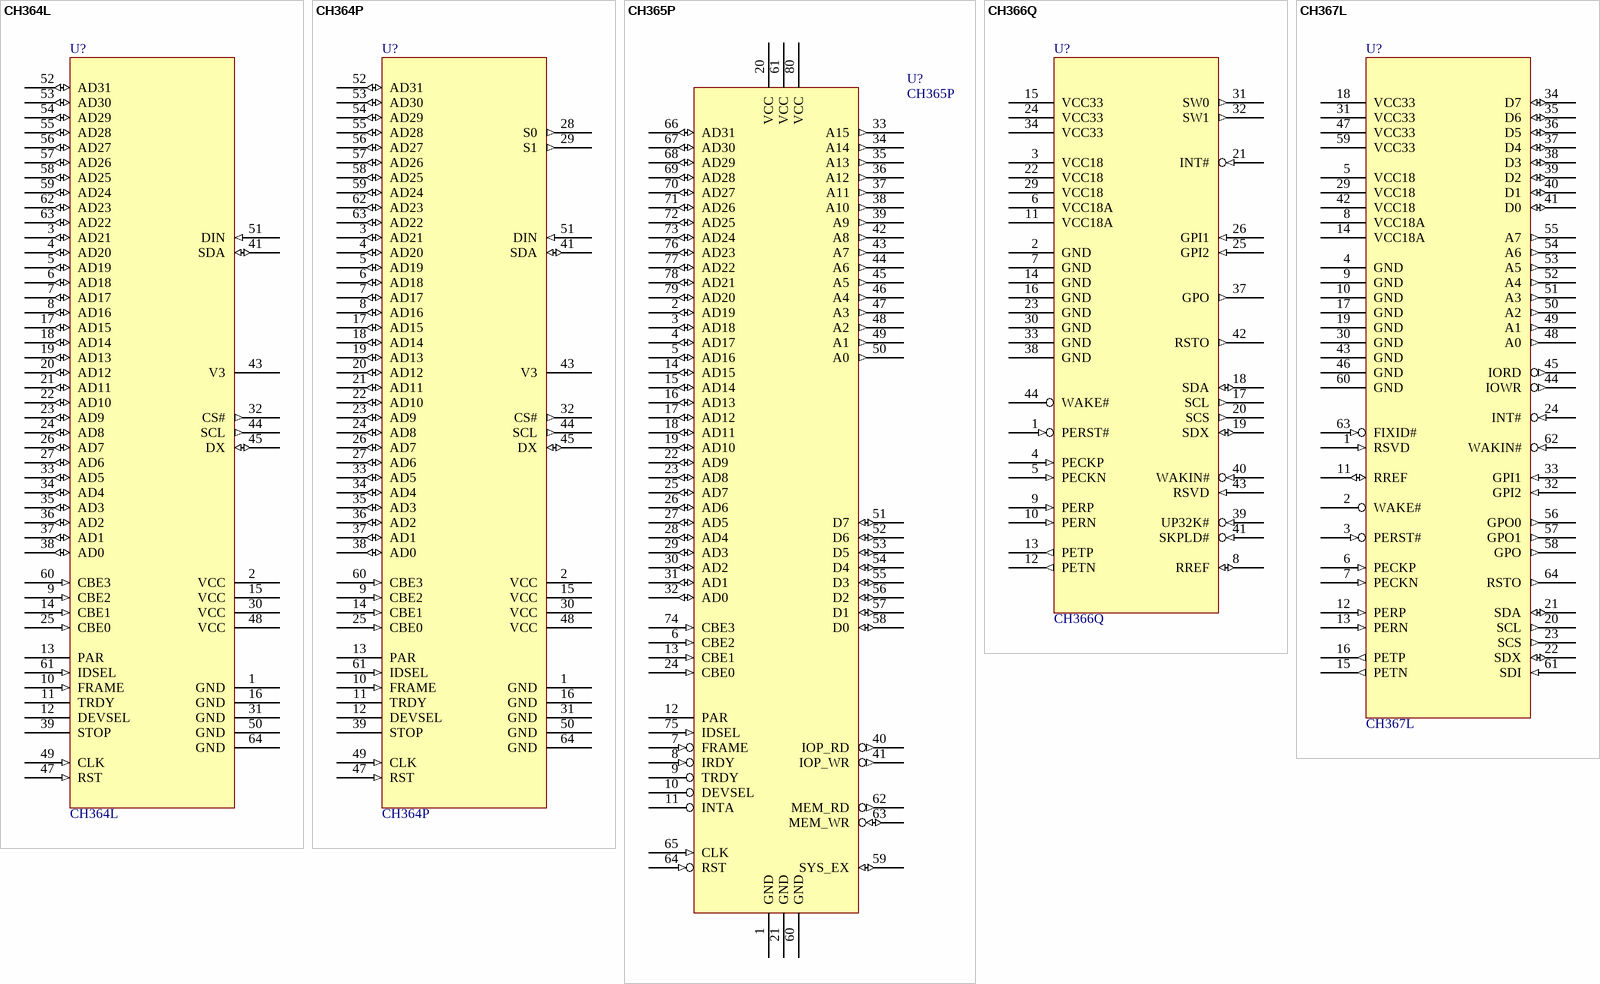
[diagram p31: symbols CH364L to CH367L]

## CH364L
designator U?
PCI Device / Slave Embedded Flash ROM, for Expansion ROM
footprint QFP64
pins: 1 GND (power), 2 VCC (power), 3 AD21 (io), 4 AD20 (io), 5 AD19 (io), 6 AD18 (io), 7 AD17 (io), 8 AD16 (io), 9 CBE2 (in), 10 FRAME (in), 11 TRDY (hiz), 12 DEVSEL (hiz), 13 PAR (hiz), 14 CBE1 (in), 15 VCC (power), 16 GND (power), 17 AD15 (io), 18 AD14 (io), 19 AD13 (io), 20 AD12 (io), 21 AD11 (io), 22 AD10 (io), 23 AD9 (io), 24 AD8 (io), 25 CBE0 (in), 26 AD7 (io), 27 AD6 (io), 30 VCC (power), 31 GND (power), 32 CS# (out), 33 AD5 (io), 34 AD4 (io), 35 AD3 (io), 36 AD2 (io), 37 AD1 (io), 38 AD0 (io), 39 STOP (hiz), 41 SDA (io), 43 V3 (power), 44 SCL (out), 45 DX (io), 47 RST (in), 48 VCC (power), 49 CLK (in), 50 GND (power), 51 DIN (in), 52 AD31 (io), 53 AD30 (io), 54 AD29 (io), 55 AD28 (io), 56 AD27 (io), 57 AD26 (io), 58 AD25 (io), 59 AD24 (io), 60 CBE3 (in), 61 IDSEL (in), 62 AD23 (io), 63 AD22 (io), 64 GND (power)

## CH364P
designator U?
PCI Device / Slave Embedded Flash ROM, for Expansion ROM with control
footprint QFP64
pins: 1 GND (power), 2 VCC (power), 3 AD21 (io), 4 AD20 (io), 5 AD19 (io), 6 AD18 (io), 7 AD17 (io), 8 AD16 (io), 9 CBE2 (in), 10 FRAME (in), 11 TRDY (hiz), 12 DEVSEL (hiz), 13 PAR (hiz), 14 CBE1 (in), 15 VCC (power), 16 GND (power), 17 AD15 (io), 18 AD14 (io), 19 AD13 (io), 20 AD12 (io), 21 AD11 (io), 22 AD10 (io), 23 AD9 (io), 24 AD8 (io), 25 CBE0 (in), 26 AD7 (io), 27 AD6 (io), 28 S0 (out), 29 S1 (out), 30 VCC (power), 31 GND (power), 32 CS# (out), 33 AD5 (io), 34 AD4 (io), 35 AD3 (io), 36 AD2 (io), 37 AD1 (io), 38 AD0 (io), 39 STOP (hiz), 41 SDA (io), 43 V3 (power), 44 SCL (out), 45 DX (io), 47 RST (in), 48 VCC (power), 49 CLK (in), 50 GND (power), 51 DIN (in), 52 AD31 (io), 53 AD30 (io), 54 AD29 (io), 55 AD28 (io), 56 AD27 (io), 57 AD26 (io), 58 AD25 (io), 59 AD24 (io), 60 CBE3 (in), 61 IDSEL (in), 62 AD23 (io), 63 AD22 (io), 64 GND (power)

## CH365P
designator U?
PCI Device / Slave, for I/O port or RAM / ROM
footprint PQFP80
pins: 1 GND (power), 2 AD19 (io), 3 AD18 (io), 4 AD17 (io), 5 AD16 (io), 6 CBE2 (in), 7 FRAME (in), 8 IRDY (in), 9 TRDY (hiz), 10 DEVSEL (hiz), 11 INTA (hiz), 12 PAR (hiz), 13 CBE1 (in), 14 AD15 (io), 15 AD14 (io), 16 AD13 (io), 17 AD12 (io), 18 AD11 (io), 19 AD10 (io), 20 VCC (power), 21 GND (power), 22 AD9 (io), 23 AD8 (io), 24 CBE0 (in), 25 AD7 (io), 26 AD6 (io), 27 AD5 (io), 28 AD4 (io), 29 AD3 (io), 30 AD2 (io), 31 AD1 (io), 32 AD0 (io), 33 A15 (out), 34 A14 (out), 35 A13 (out), 36 A12 (out), 37 A11 (out), 38 A10 (out), 39 A9 (out), 40 IOP_RD (out), 41 IOP_WR (out), 42 A8 (out), 43 A7 (out), 44 A6 (out), 45 A5 (out), 46 A4 (out), 47 A3 (out), 48 A2 (out), 49 A1 (out), 50 A0 (out), 51 D7 (io), 52 D6 (io), 53 D5 (io), 54 D4 (io), 55 D3 (io), 56 D2 (io), 57 D1 (io), 58 D0 (io), 59 SYS_EX (io), 60 GND (power), 61 VCC (power), 62 MEM_RD (out), 63 MEM_WR (io), 64 RST (in), 65 CLK (in), 66 AD31 (io), 67 AD30 (io), 68 AD29 (io), 69 AD28 (io), 70 AD27 (io), 71 AD26 (io), 72 AD25 (io), 73 AD24 (io), 74 CBE3 (in), 75 IDSEL (in), 76 AD23 (io), 77 AD22 (io), 78 AD21 (io), 79 AD20 (io), 80 VCC (power)

## CH366Q
designator U?
PCIe Expansion ROM Controller
footprint LQFP44
pins: 1 PERST# (in), 2 GND (power), 3 VCC18 (power), 4 PECKP (in), 5 PECKN (in), 6 VCC18A (power), 7 GND (power), 8 RREF (io), 9 PERP (in), 10 PERN (in), 11 VCC18A (power), 12 PETN (out), 13 PETP (out), 14 GND (power), 15 VCC33 (power), 16 GND (power), 17 SCL (out), 18 SDA (io), 19 SDX (io), 20 SCS (out), 21 INT# (in), 22 VCC18 (power), 23 GND (power), 24 VCC33 (power), 25 GPI2 (in), 26 GPI1 (in), 29 VCC18 (power), 30 GND (power), 31 SW0 (out), 32 SW1 (out), 33 GND (power), 34 VCC33 (power), 37 GPO (out), 38 GND (power), 39 UP32K# (in), 40 WAKIN# (in), 41 SKPLD# (in), 42 RSTO (out), 43 RSVD (in), 44 WAKE# (oc)

## CH367L
designator U?
PCIe to 8-bit Local Bus, Support I/O Port
footprint LQFP64
pins: 1 RSVD (in), 2 WAKE# (oc), 3 PERST# (in), 4 GND (power), 5 VCC18 (power), 6 PECKP (in), 7 PECKN (in), 8 VCC18A (power), 9 GND (power), 10 GND (power), 11 RREF (io), 12 PERP (in), 13 PERN (in), 14 VCC18A (power), 15 PETN (out), 16 PETP (out), 17 GND (power), 18 VCC33 (power), 19 GND (power), 20 SCL (out), 21 SDA (io), 22 SDX (io), 23 SCS (out), 24 INT# (in), 29 VCC18 (power), 30 GND (power), 31 VCC33 (power), 32 GPI2 (in), 33 GPI1 (in), 34 D7 (io), 35 D6 (io), 36 D5 (io), 37 D4 (io), 38 D3 (io), 39 D2 (io), 40 D1 (io), 41 D0 (io), 42 VCC18 (power), 43 GND (power), 44 IOWR (out), 45 IORD (out), 46 GND (power), 47 VCC33 (power), 48 A0 (out), 49 A1 (out), 50 A2 (out), 51 A3 (out), 52 A4 (out), 53 A5 (out), 54 A6 (out), 55 A7 (out), 56 GPO0 (out), 57 GPO1 (out), 58 GPO (out), 59 VCC33 (power), 60 GND (power), 61 SDI (in), 62 WAKIN# (in), 63 FIXID# (in), 64 RSTO (out)

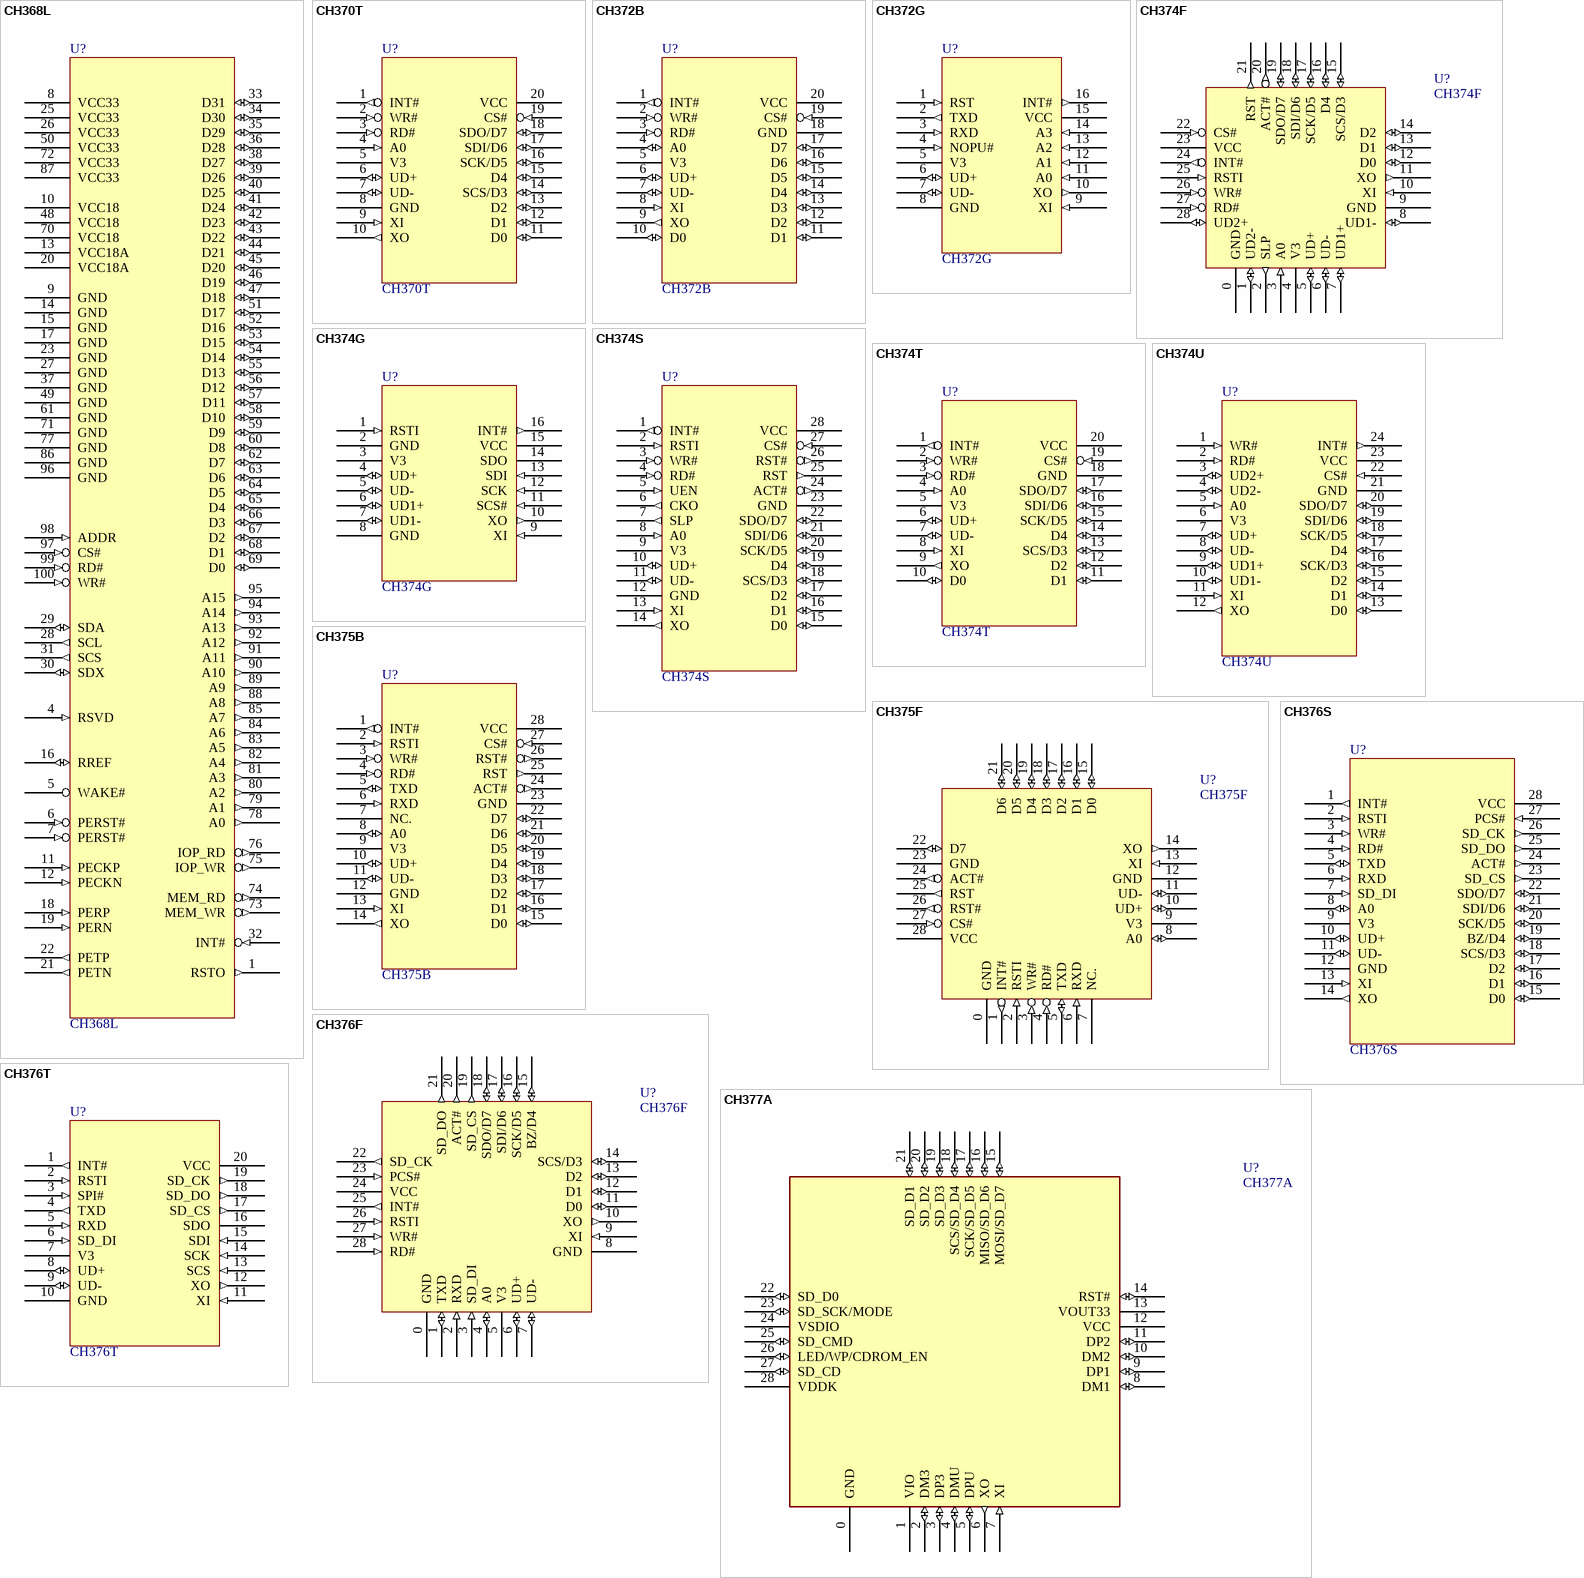
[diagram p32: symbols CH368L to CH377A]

## CH368L
designator U?
PCIe to 32-bit Local Bus, Support I/O Port and Memory
footprint LQFP100
pins: 1 RSTO (out), 4 RSVD (in), 5 WAKE# (oc), 6 PERST# (in), 7 PERST# (in), 8 VCC33 (power), 9 GND (power), 10 VCC18 (power), 11 PECKP (in), 12 PECKN (in), 13 VCC18A (power), 14 GND (power), 15 GND (power), 16 RREF (io), 17 GND (power), 18 PERP (in), 19 PERN (in), 20 VCC18A (power), 21 PETN (out), 22 PETP (out), 23 GND (power), 25 VCC33 (power), 26 VCC33 (power), 27 GND (power), 28 SCL (out), 29 SDA (io), 30 SDX (io), 31 SCS (out), 32 INT# (in), 33 D31 (io), 34 D30 (io), 35 D29 (io), 36 D28 (io), 37 GND (power), 38 D27 (io), 39 D26 (io), 40 D25 (io), 41 D24 (io), 42 D23 (io), 43 D22 (io), 44 D21 (io), 45 D20 (io), 46 D19 (io), 47 D18 (io), 48 VCC18 (power), 49 GND (power), 50 VCC33 (power), 51 D17 (io), 52 D16 (io), 53 D15 (io), 54 D14 (io), 55 D13 (io), 56 D12 (io), 57 D11 (io), 58 D10 (io), 59 D9 (io), 60 D8 (io), 61 GND (power), 62 D7 (io), 63 D6 (io), 64 D5 (io), 65 D4 (io), 66 D3 (io), 67 D2 (io), 68 D1 (io), 69 D0 (io), 70 VCC18 (power), 71 GND (power), 72 VCC33 (power), 73 MEM_WR (out), 74 MEM_RD (out), 75 IOP_WR (out), 76 IOP_RD (out), 77 GND (power), 78 A0 (out), 79 A1 (out), 80 A2 (out), 81 A3 (out), 82 A4 (out), 83 A5 (out), 84 A6 (out), 85 A7 (out), 86 GND (power), 87 VCC33 (power), 88 A8 (out), 89 A9 (out), 90 A10 (out), 91 A11 (out), 92 A12 (out), 93 A13 (out), 94 A14 (out), 95 A15 (out), 96 GND (power), 97 CS# (in), 98 ADDR (in), 99 RD# (in), 100 WR# (in)

## CH370T
designator U?
USB Host for MCU, parallel / SPI
footprint SSOP20
pins: 1 INT# (out), 2 WR# (in), 3 RD# (in), 4 A0 (in), 5 V3 (power), 6 UD+ (io), 7 UD- (io), 8 GND (power), 9 XI (in), 10 XO (out), 11 D0 (io), 12 D1 (io), 13 D2 (io), 14 SCS/D3 (io), 15 D4 (io), 16 SCK/D5 (io), 17 SDI/D6 (io), 18 SDO/D7 (io), 19 CS# (in), 20 VCC (power)

## CH372B
designator U?
USB Device / Slave for MCU, Parallel
footprint SSOP20
pins: 1 INT# (out), 2 WR# (in), 3 RD# (in), 4 A0 (io), 5 V3 (power), 6 UD+ (io), 7 UD- (io), 8 XI (in), 9 XO (out), 10 D0 (io), 11 D1 (io), 12 D2 (io), 13 D3 (io), 14 D4 (io), 15 D5 (io), 16 D6 (io), 17 D7 (io), 18 GND (power), 19 CS# (in), 20 VCC (power)

## CH372G
designator U?
USB Device / Slave for MCU, Serial UART
footprint SOP16
pins: 1 RST (in), 2 TXD (out), 3 RXD (in), 4 NOPU# (in), 5 V3 (power), 6 UD+ (io), 7 UD- (io), 8 GND (power), 9 XI (in), 10 XO (out), 11 A0 (in), 12 A1 (in), 13 A2 (in), 14 A3 (in), 15 VCC (power), 16 INT# (out)

## CH374F
designator U?
USB Host & Device / Slave for MCU, parallel / SPI, Embed 3 Hub
footprint QFN28_4X4
pins: 0 GND (power), 1 UD2- (io), 2 SLP (out), 3 A0 (in), 4 V3 (power), 5 UD+ (io), 6 UD- (io), 7 UD1+ (io), 8 UD1- (io), 9 GND (power), 10 XI (in), 11 XO (out), 12 D0 (io), 13 D1 (io), 14 D2 (io), 15 SCS/D3 (io), 16 D4 (io), 17 SCK/D5 (io), 18 SDI/D6 (io), 19 SDO/D7 (io), 20 ACT# (out), 21 RST (out), 22 CS# (in), 23 VCC (power), 24 INT# (out), 25 RSTI (in), 26 WR# (in), 27 RD# (in), 28 UD2+ (io)

## CH374G
designator U?
USB Host & Device / Slave for MCU, SPI
footprint SOP16
pins: 1 RSTI (in), 2 GND (power), 3 V3 (power), 4 UD+ (io), 5 UD- (io), 6 UD1+ (io), 7 UD1- (io), 8 GND (power), 9 XI (in), 10 XO (out), 11 SCS# (in), 12 SCK (in), 13 SDI (in), 14 SDO (hiz), 15 VCC (power), 16 INT# (out)

## CH374S
designator U?
USB Host & Device / Slave for MCU, parallel / SPI
footprint SOP28
footprint DIP28
pins: 1 INT# (out), 2 RSTI (in), 3 WR# (in), 4 RD# (in), 5 UEN (in), 6 CKO (out), 7 SLP (out), 8 A0 (in), 9 V3 (power), 10 UD+ (io), 11 UD- (io), 12 GND (power), 13 XI (in), 14 XO (out), 15 D0 (io), 16 D1 (io), 17 D2 (io), 18 SCS/D3 (io), 19 D4 (io), 20 SCK/D5 (io), 21 SDI/D6 (io), 22 SDO/D7 (io), 23 GND (power), 24 ACT# (out), 25 RST (out), 26 RST# (out), 27 CS# (in), 28 VCC (power)

## CH374T
designator U?
USB Host & Device / Slave for MCU, parallel / SPI
footprint SSOP20
pins: 1 INT# (out), 2 WR# (in), 3 RD# (in), 4 A0 (in), 5 V3 (power), 6 UD+ (io), 7 UD- (io), 8 XI (in), 9 XO (out), 10 D0 (io), 11 D1 (io), 12 D2 (io), 13 SCS/D3 (io), 14 D4 (io), 15 SCK/D5 (io), 16 SDI/D6 (io), 17 SDO/D7 (io), 18 GND (power), 19 CS# (in), 20 VCC (power)

## CH374U
designator U?
USB Host & Device / Slave for MCU, parallel / SPI, Embed 3 Hub
footprint SSOP24
pins: 1 WR# (in), 2 RD# (in), 3 UD2+ (io), 4 UD2- (io), 5 A0 (in), 6 V3 (power), 7 UD+ (io), 8 UD- (io), 9 UD1+ (io), 10 UD1- (io), 11 XI (in), 12 XO (out), 13 D0 (io), 14 D1 (io), 15 D2 (io), 16 SCK/D3 (io), 17 D4 (io), 18 SCK/D5 (io), 19 SDI/D6 (io), 20 SDO/D7 (io), 21 GND (power), 22 CS# (in), 23 VCC (power), 24 INT# (out)

## CH375B
designator U?
USB Host & Device / Slave for MCU, parallel / UART Serial
footprint SOP28
footprint TSSOP28
footprint DIP28
pins: 1 INT# (out), 2 RSTI (in), 3 WR# (in), 4 RD# (in), 5 TXD (io), 6 RXD (in), 7 NC., 8 A0 (io), 9 V3 (power), 10 UD+ (io), 11 UD- (io), 12 GND (power), 13 XI (in), 14 XO (out), 15 D0 (io), 16 D1 (io), 17 D2 (io), 18 D3 (io), 19 D4 (io), 20 D5 (io), 21 D6 (io), 22 D7 (io), 23 GND (power), 24 ACT# (out), 25 RST (out), 26 RST# (out), 27 CS# (in), 28 VCC (power)

## CH375F
designator U?
USB Host & Device / Slave for MCU, parallel / UART Serial
footprint QFN28_4X4
pins: 0 GND (power), 1 INT# (out), 2 RSTI (in), 3 WR# (in), 4 RD# (in), 5 TXD (io), 6 RXD (in), 7 NC., 8 A0 (io), 9 V3 (power), 10 UD+ (io), 11 UD- (io), 12 GND (power), 13 XI (in), 14 XO (out), 15 D0 (io), 16 D1 (io), 17 D2 (io), 18 D3 (io), 19 D4 (io), 20 D5 (io), 21 D6 (io), 22 D7 (io), 23 GND (power), 24 ACT# (out), 25 RST (out), 26 RST# (out), 27 CS# (in), 28 VCC (power)

## CH376F
designator U?
USB Host and SD card Host with File System & USB Device for MCU, parallel / SPI / UART Serial
footprint QFN28_4X4
pins: 0 GND (power), 1 TXD (io), 2 RXD (in), 3 SD_DI (in), 4 A0 (io), 5 V3 (power), 6 UD+ (io), 7 UD- (io), 8 GND (power), 9 XI (in), 10 XO (out), 11 D0 (io), 12 D1 (io), 13 D2 (io), 14 SCS/D3 (io), 15 BZ/D4 (io), 16 SCK/D5 (io), 17 SDI/D6 (io), 18 SDO/D7 (io), 19 SD_CS (out), 20 ACT# (out), 21 SD_DO (out), 22 SD_CK (out), 23 PCS# (in), 24 VCC (power), 25 INT# (out), 26 RSTI (in), 27 WR# (in), 28 RD# (in)

## CH376S
designator U?
USB Host and SD card Host with File System & USB Device for MCU, parallel / SPI / UART Serial
footprint SOP28
footprint DIP28
pins: 1 INT# (out), 2 RSTI (in), 3 WR# (in), 4 RD# (in), 5 TXD (io), 6 RXD (in), 7 SD_DI (in), 8 A0 (io), 9 V3 (power), 10 UD+ (io), 11 UD- (io), 12 GND (power), 13 XI (in), 14 XO (out), 15 D0 (io), 16 D1 (io), 17 D2 (io), 18 SCS/D3 (io), 19 BZ/D4 (io), 20 SCK/D5 (io), 21 SDI/D6 (io), 22 SDO/D7 (io), 23 SD_CS (out), 24 ACT# (out), 25 SD_DO (out), 26 SD_CK (out), 27 PCS# (in), 28 VCC (power)

## CH376T
designator U?
USB Host and SD card Host with File System & USB Device for MCU, SPI / UART Serial
footprint SSOP20
pins: 1 INT# (out), 2 RSTI (in), 3 SPI# (in), 4 TXD (out), 5 RXD (in), 6 SD_DI (in), 7 V3 (power), 8 UD+ (io), 9 UD- (io), 10 GND (power), 11 XI (in), 12 XO (out), 13 SCS (in), 14 SCK (in), 15 SDI (in), 16 SDO (hiz), 17 SD_CS (out), 18 SD_DO (out), 19 SD_CK (out), 20 VCC (power)

## CH377A
designator U?
USB SD card Reader & 3 ports USB 2.0 HS Hub
footprint QFN28_4X4 (Footprint not found)
pins: 0 GND (power), 1 VIO (power), 2 DM3 (io), 3 DP3 (io), 4 DMU (io), 5 DPU (io), 6 XO (out), 7 XI (in), 8 DM1 (io), 9 DP1 (io), 10 DM2 (io), 11 DP2 (io), 12 VCC (power), 13 VOUT33 (power), 14 RST# (io), 15 MOSI/SD_D7 (io), 16 MISO/SD_D6 (io), 17 SCK/SD_D5 (io), 18 SCS/SD_D4 (io), 19 SD_D3 (io), 20 SD_D2 (io), 21 SD_D1 (io), 22 SD_D0 (io), 23 SD_SCK/MODE (io), 24 VSDIO (power), 25 SD_CMD (io), 26 LED/WP/CDROM_EN (io), 27 SD_CD (io), 28 VDDK (power)

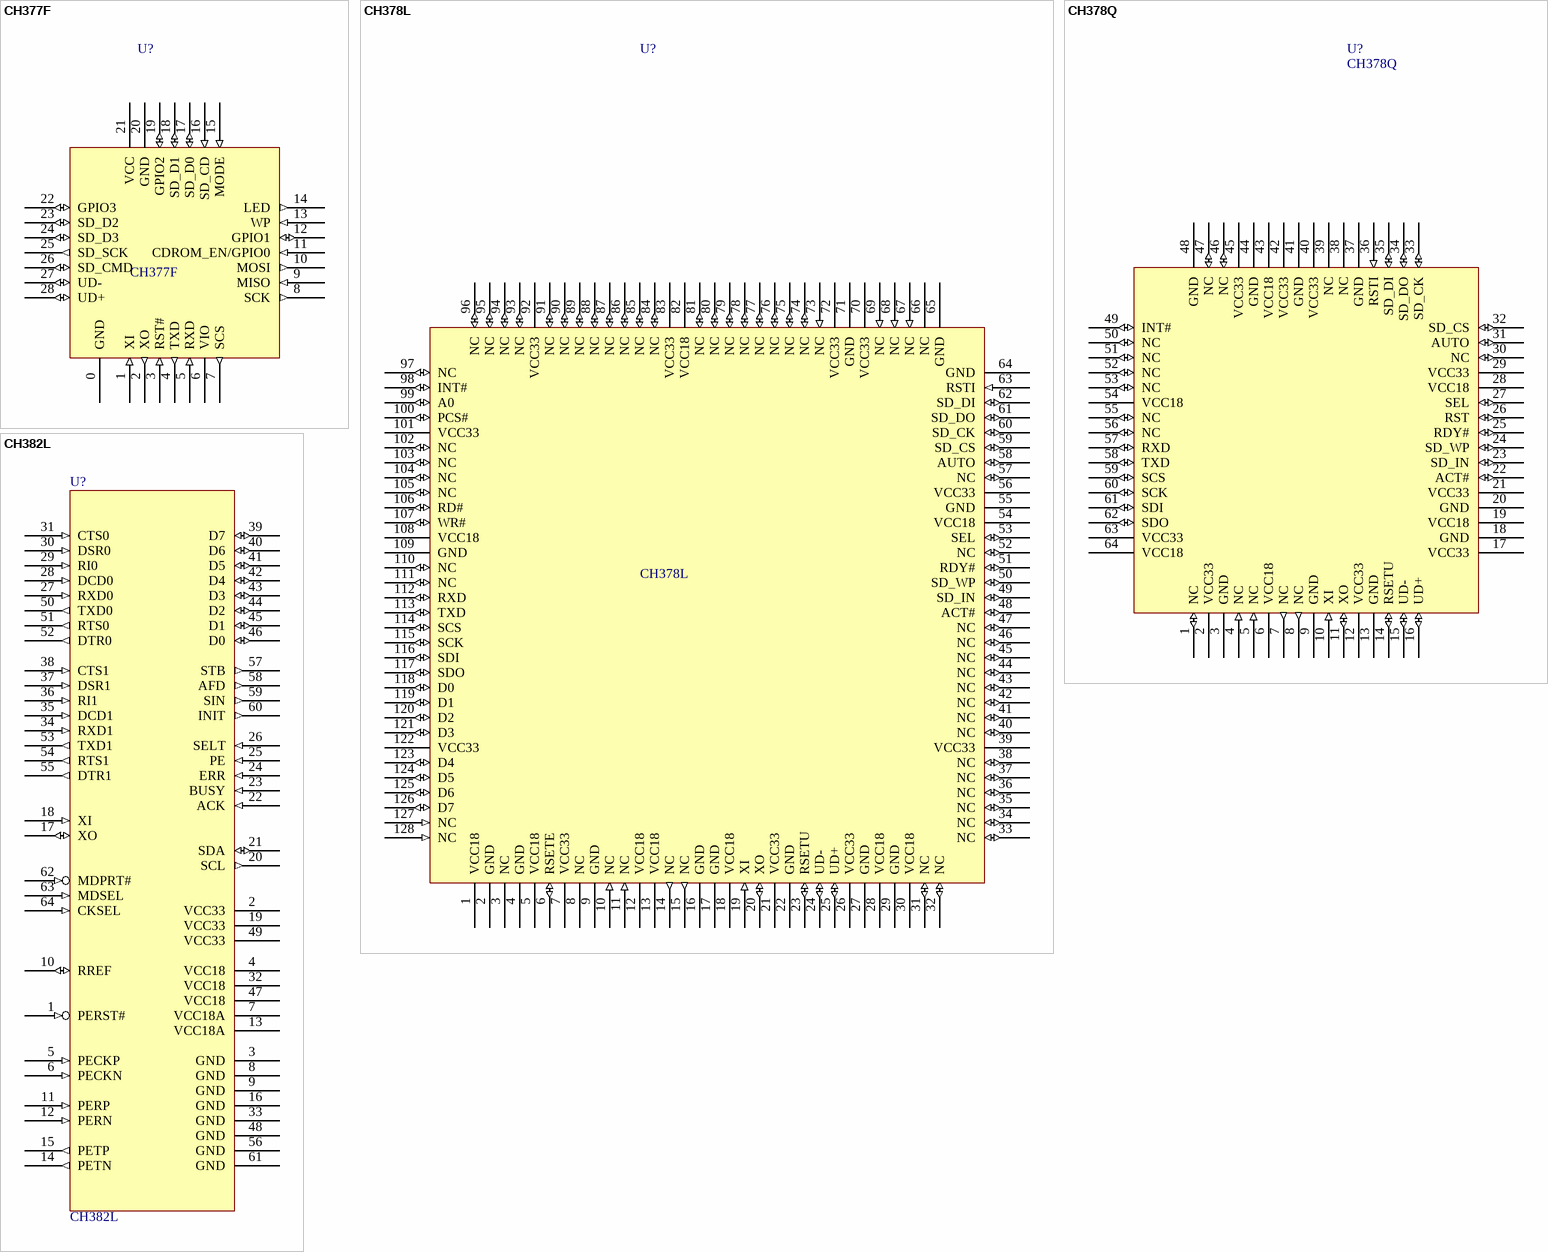
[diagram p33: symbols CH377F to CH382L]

## CH377F
designator U?
USB SD card Reader
footprint QFN28_4X4
pins: 0 GND (power), 1 XI (in), 2 XO (out), 3 RST# (in), 4 TXD (out), 5 RXD (in), 6 VIO (power), 7 SCS (out), 8 SCK (out), 9 MISO (in), 10 MOSI (out), 11 CDROM_EN/GPIO0 (in), 12 GPIO1 (io), 13 WP (in), 14 LED (out), 15 MODE (in), 16 SD_CD (in), 17 SD_D0 (io), 18 SD_D1 (io), 19 GPIO2 (io), 20 GND (power), 21 VCC (power), 22 GPIO3 (io), 23 SD_D2 (io), 24 SD_D3 (io), 25 SD_SCK (out), 26 SD_CMD (io), 27 UD- (io), 28 UD+ (io)

## CH378L
designator U?
USB2.0 Host with File System & USB Device for MCU, parallel / SPI / UART Serial
footprint LQFP128
pins: 1 VCC18 (power), 2 GND (power), 3 NC, 4 GND (power), 5 VCC18 (power), 6 RSETE (io), 7 VCC33 (power), 8 NC, 9 GND (power), 10 NC (in), 11 NC (in), 12 VCC18 (power), 13 VCC18 (power), 14 NC (out), 15 NC (out), 16 GND (power), 17 GND (power), 18 VCC18 (power), 19 XI (in), 20 XO (io), 21 VCC33 (power), 22 GND (power), 23 RSETU (io), 24 UD- (io), 25 UD+ (io), 26 VCC33 (power), 27 GND (power), 28 VCC18 (power), 29 GND (power), 30 VCC18 (power), 31 NC (io), 32 NC (io), 33 NC (io), 34 NC (io), 35 NC (io), 36 NC (io), 37 NC (io), 38 NC (io), 39 VCC33 (power), 40 NC (io), 41 NC (io), 42 NC (io), 43 NC (io), 44 NC (io), 45 NC (io), 46 NC (io), 47 NC (io), 48 ACT# (io), 49 SD_IN (io), 50 SD_WP (io), 51 RDY# (io), 52 NC (io), 53 SEL (io), 54 VCC18 (power), 55 GND (power), 56 VCC33 (power), 57 NC (io), 58 AUTO (io), 59 SD_CS (io), 60 SD_CK (io), 61 SD_DO (io), 62 SD_DI (io), 63 RSTI (in), 64 GND (power), 65 GND (power), 66 NC (power), 67 NC (in), 68 NC (in), 69 NC (in), 70 VCC33 (power), 71 GND (power), 72 VCC33 (power), 73 NC (in), 74 NC (io), 75 NC (io), 76 NC (io), 77 NC (io), 78 NC (io), 79 NC (io), 80 NC (io), 81 NC (io), 82 VCC18 (power), 83 VCC33 (power), 84 NC (io), 85 NC (io), 86 NC (io), 87 NC (io), 88 NC (io), 89 NC (io), 90 NC (io), 91 NC (io), 92 VCC33 (power), 93 NC (io), 94 NC (io), 95 NC (io), 96 NC (io), 97 NC (io), 98 INT# (io), 99 A0 (io), 100 PCS# (io), 101 VCC33 (power), 102 NC (io), 103 NC (io), 104 NC (io), 105 NC (io), 106 RD# (io), 107 WR# (io), 108 VCC18 (power), 109 GND (power), 110 NC (io), 111 NC (io), 112 RXD (io), 113 TXD (io), 114 SCS (io), 115 SCK (io), 116 SDI (io), 117 SDO (io), 118 D0 (io), 119 D1 (io), 120 D2 (io), 121 D3 (io), 122 VCC33 (power), 123 D4 (io), 124 D5 (io), 125 D6 (io), 126 D7 (io), 127 NC (in), 128 NC (in)

## CH378Q
designator U?
USB2.0 Host with File System & USB Device for MCU, parallel / SPI / UART Serial
footprint LQFP64M_10X10
pins: 1 NC (io), 2 VCC33 (power), 3 GND (power), 4 NC (in), 5 NC (in), 6 VCC18 (power), 7 NC (out), 8 NC (out), 9 GND (power), 10 XI (in), 11 XO (io), 12 VCC33 (power), 13 GND (power), 14 RSETU (io), 15 UD- (io), 16 UD+ (io), 17 VCC33 (power), 18 GND (power), 19 VCC18 (power), 20 GND (power), 21 VCC33 (power), 22 ACT# (io), 23 SD_IN (io), 24 SD_WP (io), 25 RDY# (io), 26 RST (io), 27 SEL (io), 28 VCC18 (power), 29 VCC33 (power), 30 NC (io), 31 AUTO (io), 32 SD_CS (io), 33 SD_CK (io), 34 SD_DO (io), 35 SD_DI (io), 36 RSTI (in), 37 GND (power), 38 NC (power), 39 NC, 40 VCC33 (power), 41 GND (power), 42 VCC33 (power), 43 VCC18 (power), 44 GND (power), 45 VCC33 (power), 46 NC (io), 47 NC (io), 48 GND (power), 49 INT# (io), 50 NC (io), 51 NC (io), 52 NC (io), 53 NC (io), 54 VCC18 (power), 55 NC (io), 56 NC (io), 57 RXD (io), 58 TXD (io), 59 SCS (io), 60 SCK (io), 61 SDI (io), 62 SDO (io), 63 VCC33 (power), 64 VCC18 (power)

## CH382L
designator U?
PCIe to 2S1P: Print Port / Parallel and Dual 16C550 UART with 256 byte FIFO
footprint LQFP64
pins: 1 PERST# (in), 2 VCC33 (power), 3 GND (power), 4 VCC18 (power), 5 PECKP (in), 6 PECKN (in), 7 VCC18A (power), 8 GND (power), 9 GND (power), 10 RREF (io), 11 PERP (in), 12 PERN (in), 13 VCC18A (power), 14 PETN (out), 15 PETP (out), 16 GND (power), 17 XO (io), 18 XI (in), 19 VCC33 (power), 20 SCL (out), 21 SDA (io), 22 ACK (in), 23 BUSY (in), 24 ERR (in), 25 PE (in), 26 SELT (in), 27 RXD0 (in), 28 DCD0 (in), 29 RI0 (in), 30 DSR0 (in), 31 CTS0 (in), 32 VCC18 (power), 33 GND (power), 34 RXD1 (in), 35 DCD1 (in), 36 RI1 (in), 37 DSR1 (in), 38 CTS1 (in), 39 D7 (io), 40 D6 (io), 41 D5 (io), 42 D4 (io), 43 D3 (io), 44 D2 (io), 45 D1 (io), 46 D0 (io), 47 VCC18 (power), 48 GND (power), 49 VCC33 (power), 50 TXD0 (out), 51 RTS0 (out), 52 DTR0 (out), 53 TXD1 (out), 54 RTS1 (out), 55 DTR1 (out), 56 GND (power), 57 STB (out), 58 AFD (out), 59 SIN (out), 60 INIT (out), 61 GND (power), 62 MDPRT# (in), 63 MDSEL (in), 64 CKSEL (in)

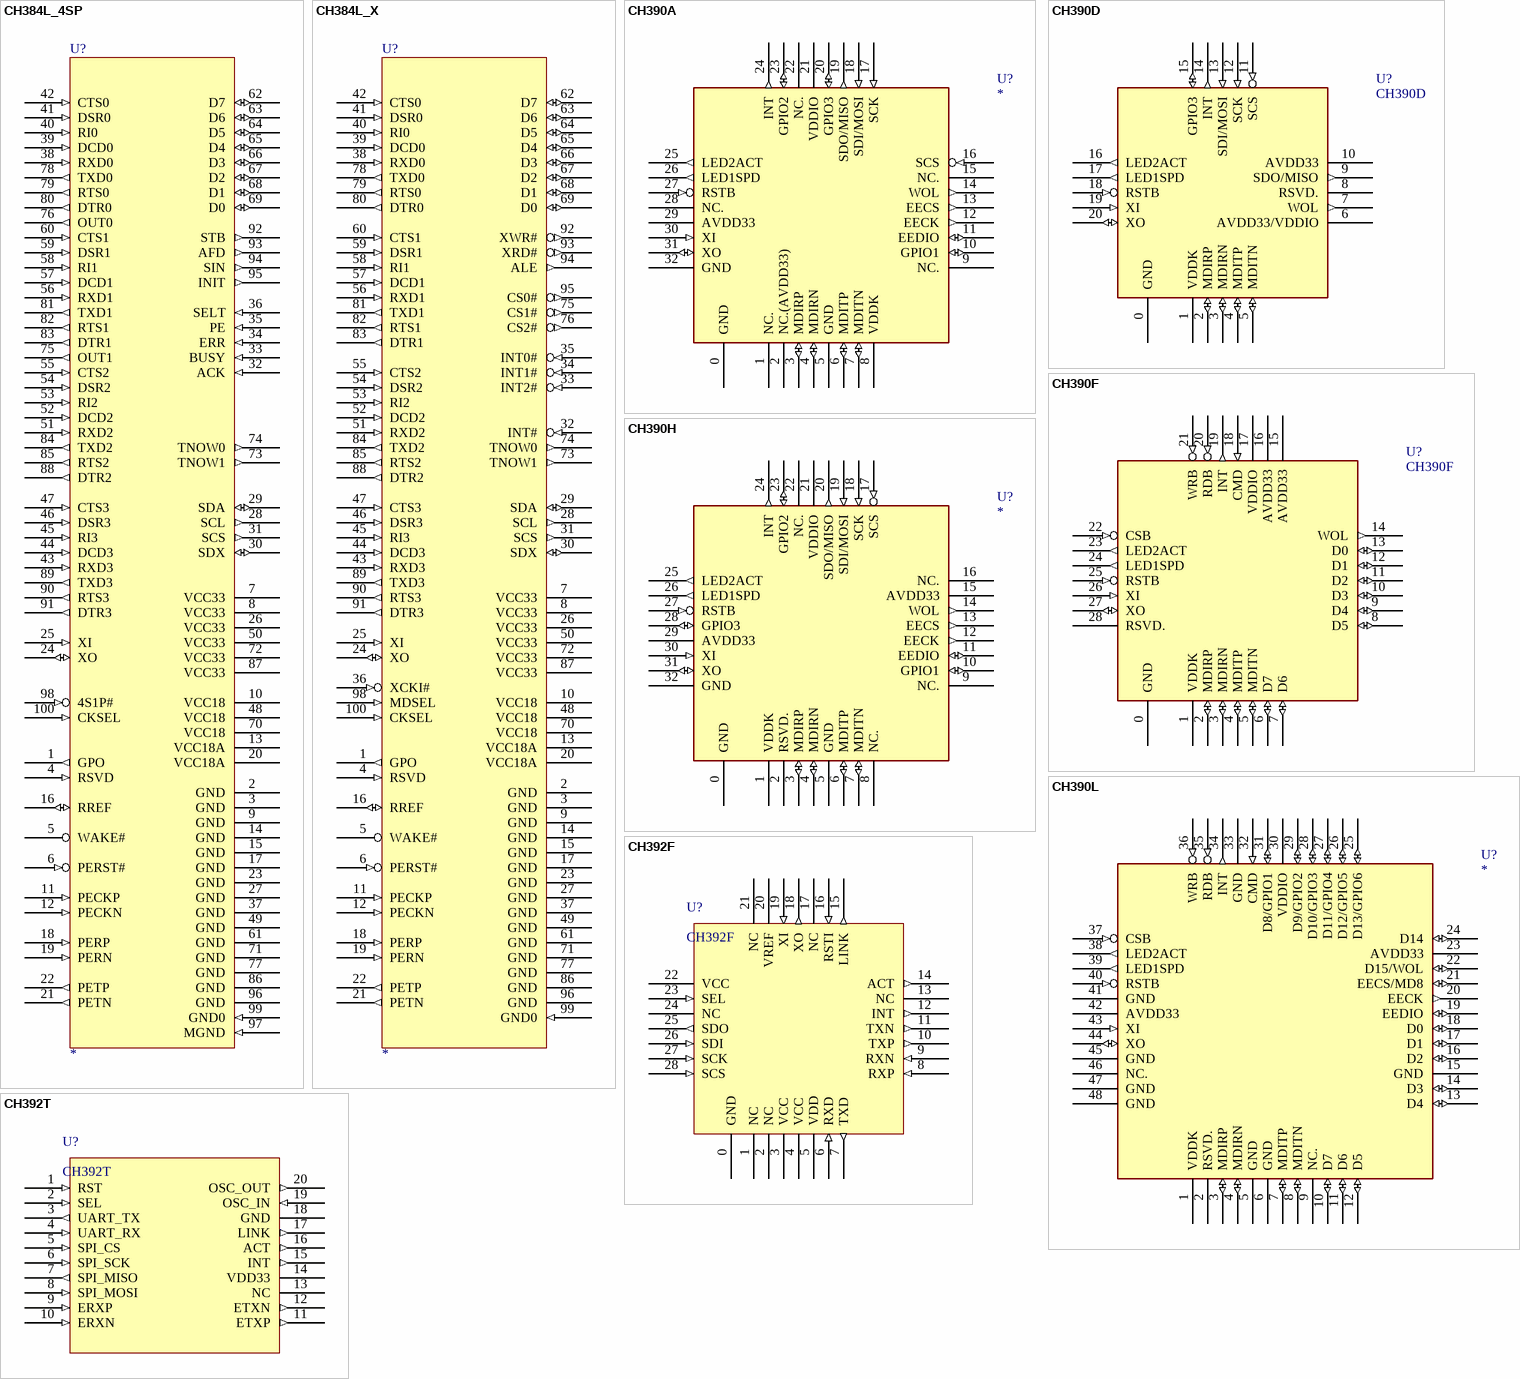
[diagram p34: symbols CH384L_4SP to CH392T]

## CH384L_4SP
designator U?
PCIe to 4S1P: Print Port / Parallel and Quad 16C550 UART with 256 byte FIFO
footprint LQFP100
pins: 1 GPO (out), 2 GND (power), 3 GND (power), 4 RSVD (in), 5 WAKE# (oc), 6 PERST# (in), 7 VCC33 (power), 8 VCC33 (power), 9 GND (power), 10 VCC18 (power), 11 PECKP (in), 12 PECKN (in), 13 VCC18A (power), 14 GND (power), 15 GND (power), 16 RREF (io), 17 GND (power), 18 PERP (in), 19 PERN (in), 20 VCC18A (power), 21 PETN (out), 22 PETP (out), 23 GND (power), 24 XO (io), 25 XI (in), 26 VCC33 (power), 27 GND (power), 28 SCL (out), 29 SDA (io), 30 SDX (io), 31 SCS (out), 32 ACK (in), 33 BUSY (in), 34 ERR (in), 35 PE (in), 36 SELT (in), 37 GND (power), 38 RXD0 (in), 39 DCD0 (in), 40 RI0 (in), 41 DSR0 (in), 42 CTS0 (in), 43 RXD3 (in), 44 DCD3 (in), 45 RI3 (in), 46 DSR3 (in), 47 CTS3 (in), 48 VCC18 (power), 49 GND (power), 50 VCC33 (power), 51 RXD2 (in), 52 DCD2 (in), 53 RI2 (in), 54 DSR2 (in), 55 CTS2 (in), 56 RXD1 (in), 57 DCD1 (in), 58 RI1 (in), 59 DSR1 (in), 60 CTS1 (in), 61 GND (power), 62 D7 (io), 63 D6 (io), 64 D5 (io), 65 D4 (io), 66 D3 (io), 67 D2 (io), 68 D1 (io), 69 D0 (io), 70 VCC18 (power), 71 GND (power), 72 VCC33 (power), 73 TNOW1 (out), 74 TNOW0 (out), 75 OUT1 (out), 76 OUT0 (out), 77 GND (power), 78 TXD0 (out), 79 RTS0 (out), 80 DTR0 (out), 81 TXD1 (out), 82 RTS1 (out), 83 DTR1 (out), 84 TXD2 (out), 85 RTS2 (out), 86 GND (power), 87 VCC33 (power), 88 DTR2 (out), 89 TXD3 (out), 90 RTS3 (out), 91 DTR3 (out), 92 STB (out), 93 AFD (out), 94 SIN (out), 95 INIT (out), 96 GND (power), 97 MGND (in), 98 4S1P# (in), 99 GND0 (in), 100 CKSEL (in)

## CH384L_X
designator U?
PCIe to 8S or 28S: External 8 or 24*UART
footprint LQFP100
pins: 1 GPO (out), 2 GND (power), 3 GND (power), 4 RSVD (in), 5 WAKE# (oc), 6 PERST# (in), 7 VCC33 (power), 8 VCC33 (power), 9 GND (power), 10 VCC18 (power), 11 PECKP (in), 12 PECKN (in), 13 VCC18A (power), 14 GND (power), 15 GND (power), 16 RREF (io), 17 GND (power), 18 PERP (in), 19 PERN (in), 20 VCC18A (power), 21 PETN (out), 22 PETP (out), 23 GND (power), 24 XO (io), 25 XI (in), 26 VCC33 (power), 27 GND (power), 28 SCL (out), 29 SDA (io), 30 SDX (io), 31 SCS (out), 32 INT# (in), 33 INT2# (in), 34 INT1# (in), 35 INT0# (in), 36 XCKI# (in), 37 GND (power), 38 RXD0 (in), 39 DCD0 (in), 40 RI0 (in), 41 DSR0 (in), 42 CTS0 (in), 43 RXD3 (in), 44 DCD3 (in), 45 RI3 (in), 46 DSR3 (in), 47 CTS3 (in), 48 VCC18 (power), 49 GND (power), 50 VCC33 (power), 51 RXD2 (in), 52 DCD2 (in), 53 RI2 (in), 54 DSR2 (in), 55 CTS2 (in), 56 RXD1 (in), 57 DCD1 (in), 58 RI1 (in), 59 DSR1 (in), 60 CTS1 (in), 61 GND (power), 62 D7 (io), 63 D6 (io), 64 D5 (io), 65 D4 (io), 66 D3 (io), 67 D2 (io), 68 D1 (io), 69 D0 (io), 70 VCC18 (power), 71 GND (power), 72 VCC33 (power), 73 TNOW1 (out), 74 TNOW0 (out), 75 CS1# (out), 76 CS2# (out), 77 GND (power), 78 TXD0 (out), 79 RTS0 (out), 80 DTR0 (out), 81 TXD1 (out), 82 RTS1 (out), 83 DTR1 (out), 84 TXD2 (out), 85 RTS2 (out), 86 GND (power), 87 VCC33 (power), 88 DTR2 (out), 89 TXD3 (out), 90 RTS3 (out), 91 DTR3 (out), 92 XWR# (out), 93 XRD# (out), 94 ALE (out), 95 CS0# (out), 96 GND (power), 98 MDSEL (in), 99 GND0 (in), 100 CKSEL (in)

## CH390A
designator U?
SPI to 10/100M Ethernet MAC & PHY
footprint QFN32_5X5
pins: 0 GND (power), 1 NC., 2 NC.(AVDD33), 3 MDIRP (io), 4 MDIRN (io), 5 GND (power), 6 MDITP (io), 7 MDITN (io), 8 VDDK (power), 9 NC., 10 GPIO1 (io), 11 EEDIO (io), 12 EECK (out), 13 EECS (out), 14 WOL (out), 15 NC., 16 SCS (in), 17 SCK (in), 18 SDI/MOSI (in), 19 SDO/MISO (out), 20 GPIO3 (io), 21 VDDIO (power), 22 NC., 23 GPIO2 (io), 24 INT (out), 25 LED2ACT (out), 26 LED1SPD (out), 27 RSTB (in), 28 NC., 29 AVDD33 (power), 30 XI (in), 31 XO (io), 32 GND (power)

## CH390D
designator U?
SPI to 10/100M Ethernet MAC & PHY
footprint QFN20_3X3
pins: 0 GND (power), 1 VDDK (power), 2 MDIRP (io), 3 MDIRN (io), 4 MDITP (io), 5 MDITN (io), 6 AVDD33/VDDIO (power), 7 WOL (out), 8 RSVD., 9 SDO/MISO (out), 10 AVDD33 (power), 11 SCS (in), 12 SCK (in), 13 SDI/MOSI (in), 14 INT (out), 15 GPIO3 (io), 16 LED2ACT (out), 17 LED1SPD (out), 18 RSTB (in), 19 XI (in), 20 XO (io)

## CH390F
designator U?
Parallel to 10/100M Ethernet MAC & PHY
footprint QFN28_4X4
pins: 0 GND (power), 1 VDDK (power), 2 MDIRP (io), 3 MDIRN (io), 4 MDITP (io), 5 MDITN (io), 6 D7 (io), 7 D6 (io), 8 D5 (io), 9 D4 (io), 10 D3 (io), 11 D2 (io), 12 D1 (io), 13 D0 (io), 14 WOL (out), 15 AVDD33 (power), 16 AVDD33 (power), 17 VDDIO (power), 18 CMD (in), 19 INT (out), 20 RDB (in), 21 WRB (in), 22 CSB (in), 23 LED2ACT (out), 24 LED1SPD (out), 25 RSTB (in), 26 XI (in), 27 XO (io), 28 RSVD.

## CH390H
designator U?
SPI to 10/100M Ethernet MAC & PHY
footprint QFN32_5X5
pins: 0 GND (power), 1 VDDK (power), 2 RSVD., 3 MDIRP (io), 4 MDIRN (io), 5 GND (power), 6 MDITP (io), 7 MDITN (io), 8 NC., 9 NC., 10 GPIO1 (io), 11 EEDIO (io), 12 EECK (out), 13 EECS (out), 14 WOL (out), 15 AVDD33 (power), 16 NC., 17 SCS (in), 18 SCK (in), 19 SDI/MOSI (in), 20 SDO/MISO (out), 21 VDDIO (power), 22 NC., 23 GPIO2 (io), 24 INT (out), 25 LED2ACT (out), 26 LED1SPD (out), 27 RSTB (in), 28 GPIO3 (io), 29 AVDD33 (power), 30 XI (in), 31 XO (io), 32 GND (power)

## CH390L
designator U?
Parallel to 10/100M Ethernet MAC & PHY
footprint LQFP48
pins: 1 VDDK (power), 2 RSVD., 3 MDIRP (io), 4 MDIRN (io), 5 GND (power), 6 GND (power), 7 MDITP (io), 8 MDITN (io), 9 NC., 10 D7 (io), 11 D6 (io), 12 D5 (io), 13 D4 (io), 14 D3 (io), 15 GND (power), 16 D2 (io), 17 D1 (io), 18 D0 (io), 19 EEDIO (io), 20 EECK (out), 21 EECS/MD8 (io), 22 D15/WOL (io), 23 AVDD33 (power), 24 D14 (io), 25 D13/GPIO6 (io), 26 D12/GPIO5 (io), 27 D11/GPIO4 (io), 28 D10/GPIO3 (io), 29 D9/GPIO2 (io), 30 VDDIO (power), 31 D8/GPIO1 (io), 32 CMD (in), 33 GND (power), 34 INT (out), 35 RDB (in), 36 WRB (in), 37 CSB (in), 38 LED2ACT (out), 39 LED1SPD (out), 40 RSTB (in), 41 GND (power), 42 AVDD33 (power), 43 XI (in), 44 XO (io), 45 GND (power), 46 NC., 47 GND (power), 48 GND (power)

## CH392F
designator U?
TCP/IP embedded 10M ethernet controller for MCU connecting internet, UART/SPI
footprint QFN28_4X4
pins: 0 GND (power), 1 NC, 2 NC, 3 VCC (power), 4 VCC (power), 5 VDD (power), 6 RXD (in), 7 TXD (out), 8 RXP (in), 9 RXN (in), 10 TXP (out), 11 TXN (out), 12 INT (out), 13 NC, 14 ACT (out), 15 LINK (out), 16 RSTI (in), 17 NC, 18 XO (out), 19 XI (in), 20 VREF (hiz), 21 NC, 22 VCC (power), 23 SEL (in), 24 NC, 25 SDO (out), 26 SDI (in), 27 SCK (in), 28 SCS (in)

## CH392T
designator U?
TCP/IP embedded 10M ethernet controller for MCU connecting internet, UART/SPI
footprint TSSOP20
pins: 1 RST (in), 2 SEL (in), 3 UART_TX (out), 4 UART_RX (in), 5 SPI_CS (in), 6 SPI_SCK (in), 7 SPI_MISO (out), 8 SPI_MOSI (in), 9 ERXP (in), 10 ERXN (in), 11 ETXP (out), 12 ETXN (out), 13 NC, 14 VDD33 (power), 15 INT (out), 16 ACT (out), 17 LINK (out), 18 GND (power), 19 OSC_IN (in), 20 OSC_OUT (out)

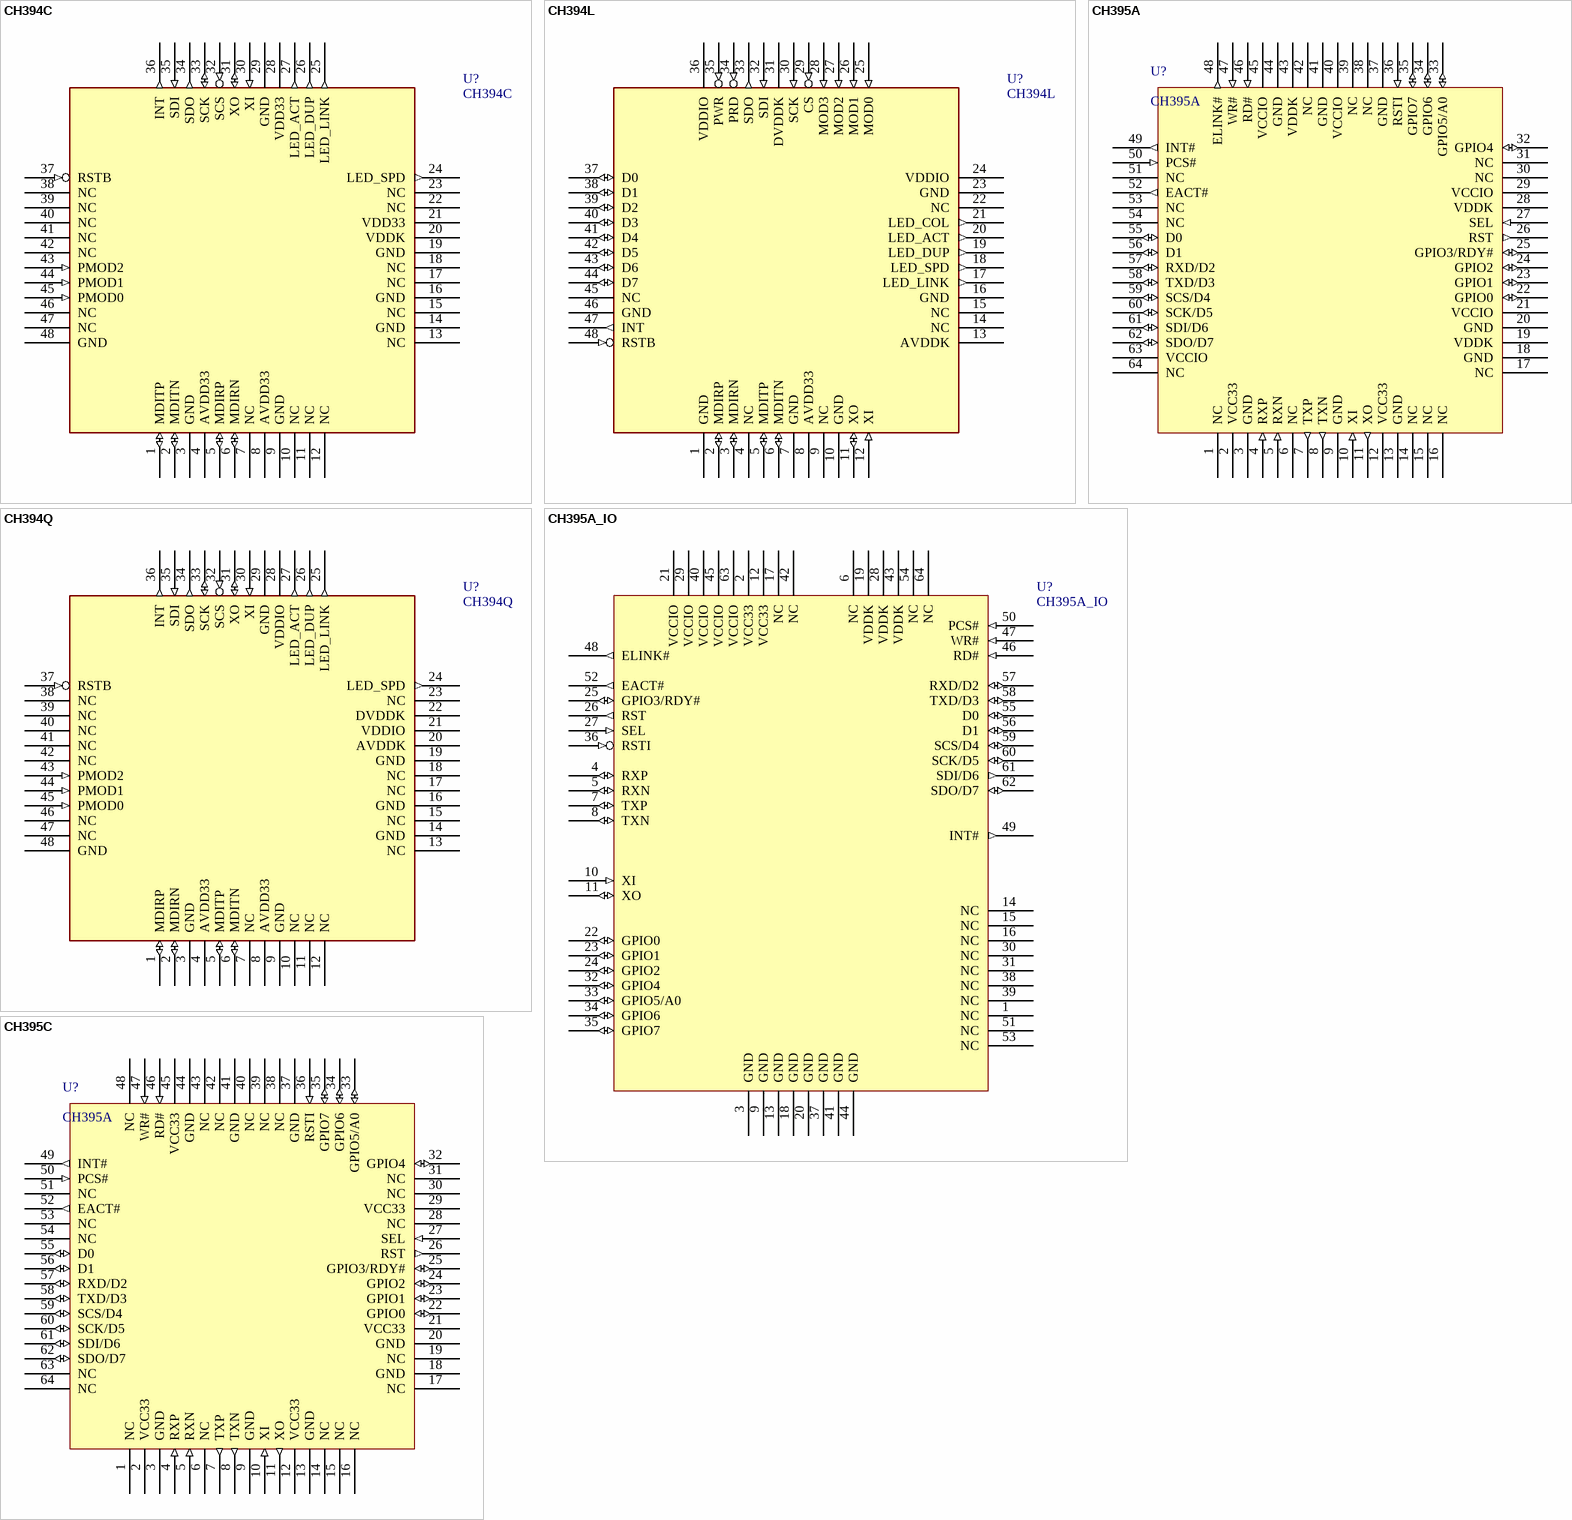
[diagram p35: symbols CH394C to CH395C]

## CH394C
designator U?
TCP/IP embedded 10M/100Mbps ethernet controller for MCU connecting internet
footprint LQFP48 (Footprint not found)
pins: 1 MDITP (io), 2 MDITN (io), 3 GND (power), 4 AVDD33 (power), 5 MDIRP (io), 6 MDIRN (io), 7 NC, 8 AVDD33 (power), 9 GND (power), 10 NC, 11 NC, 12 NC, 13 NC, 14 GND (power), 15 NC, 16 GND (power), 17 NC, 18 NC, 19 GND (power), 20 VDDK (power), 21 VDD33 (power), 22 NC, 23 NC, 24 LED_SPD (out), 25 LED_LINK (out), 26 LED_DUP (out), 27 LED_ACT (out), 28 VDD33 (power), 29 GND (power), 30 XI (in), 31 XO (io), 32 SCS (in), 33 SCK (io), 34 SDO (out), 35 SDI (in), 36 INT (out), 37 RSTB (in), 38 NC, 39 NC, 40 NC, 41 NC, 42 NC, 43 PMOD2 (in), 44 PMOD1 (in), 45 PMOD0 (in), 46 NC, 47 NC, 48 GND (power)

## CH394L
designator U?
TCP/IP embedded 10M/100Mbps ethernet controller for MCU connecting internet
footprint LQFP48 (Footprint not found)
pins: 1 GND (power), 2 MDIRP (io), 3 MDIRN (io), 4 NC, 5 MDITP (io), 6 MDITN (io), 7 GND, 8 AVDD33 (power), 9 NC, 10 GND, 11 XO (io), 12 XI (in), 13 AVDDK (power), 14 NC, 15 NC, 16 GND (power), 17 LED_LINK (out), 18 LED_SPD (out), 19 LED_DUP (out), 20 LED_ACT (out), 21 LED_COL (out), 22 NC, 23 GND (power), 24 VDDIO (power), 25 MOD0 (in), 26 MOD1 (in), 27 MOD2 (in), 28 MOD3 (in), 29 CS (in), 30 SCK (in), 31 DVDDK (power), 32 SDI (in), 33 SDO (out), 34 PRD (in), 35 PWR (in), 36 VDDIO (power), 37 D0 (io), 38 D1 (io), 39 D2 (io), 40 D3 (io), 41 D4 (io), 42 D5 (io), 43 D6 (io), 44 D7 (io), 45 NC, 46 GND (power), 47 INT (out), 48 RSTB (in)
